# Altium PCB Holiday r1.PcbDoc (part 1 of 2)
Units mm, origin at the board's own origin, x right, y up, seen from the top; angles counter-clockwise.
Board outline 67 x 67 mm, 4 copper layers (Top Layer, Mid-Layer 1, InternalPlane1, Bottom Layer), stack 1.602 mm thick; 125 components, 139 nets, 622 pads, 401 vias.
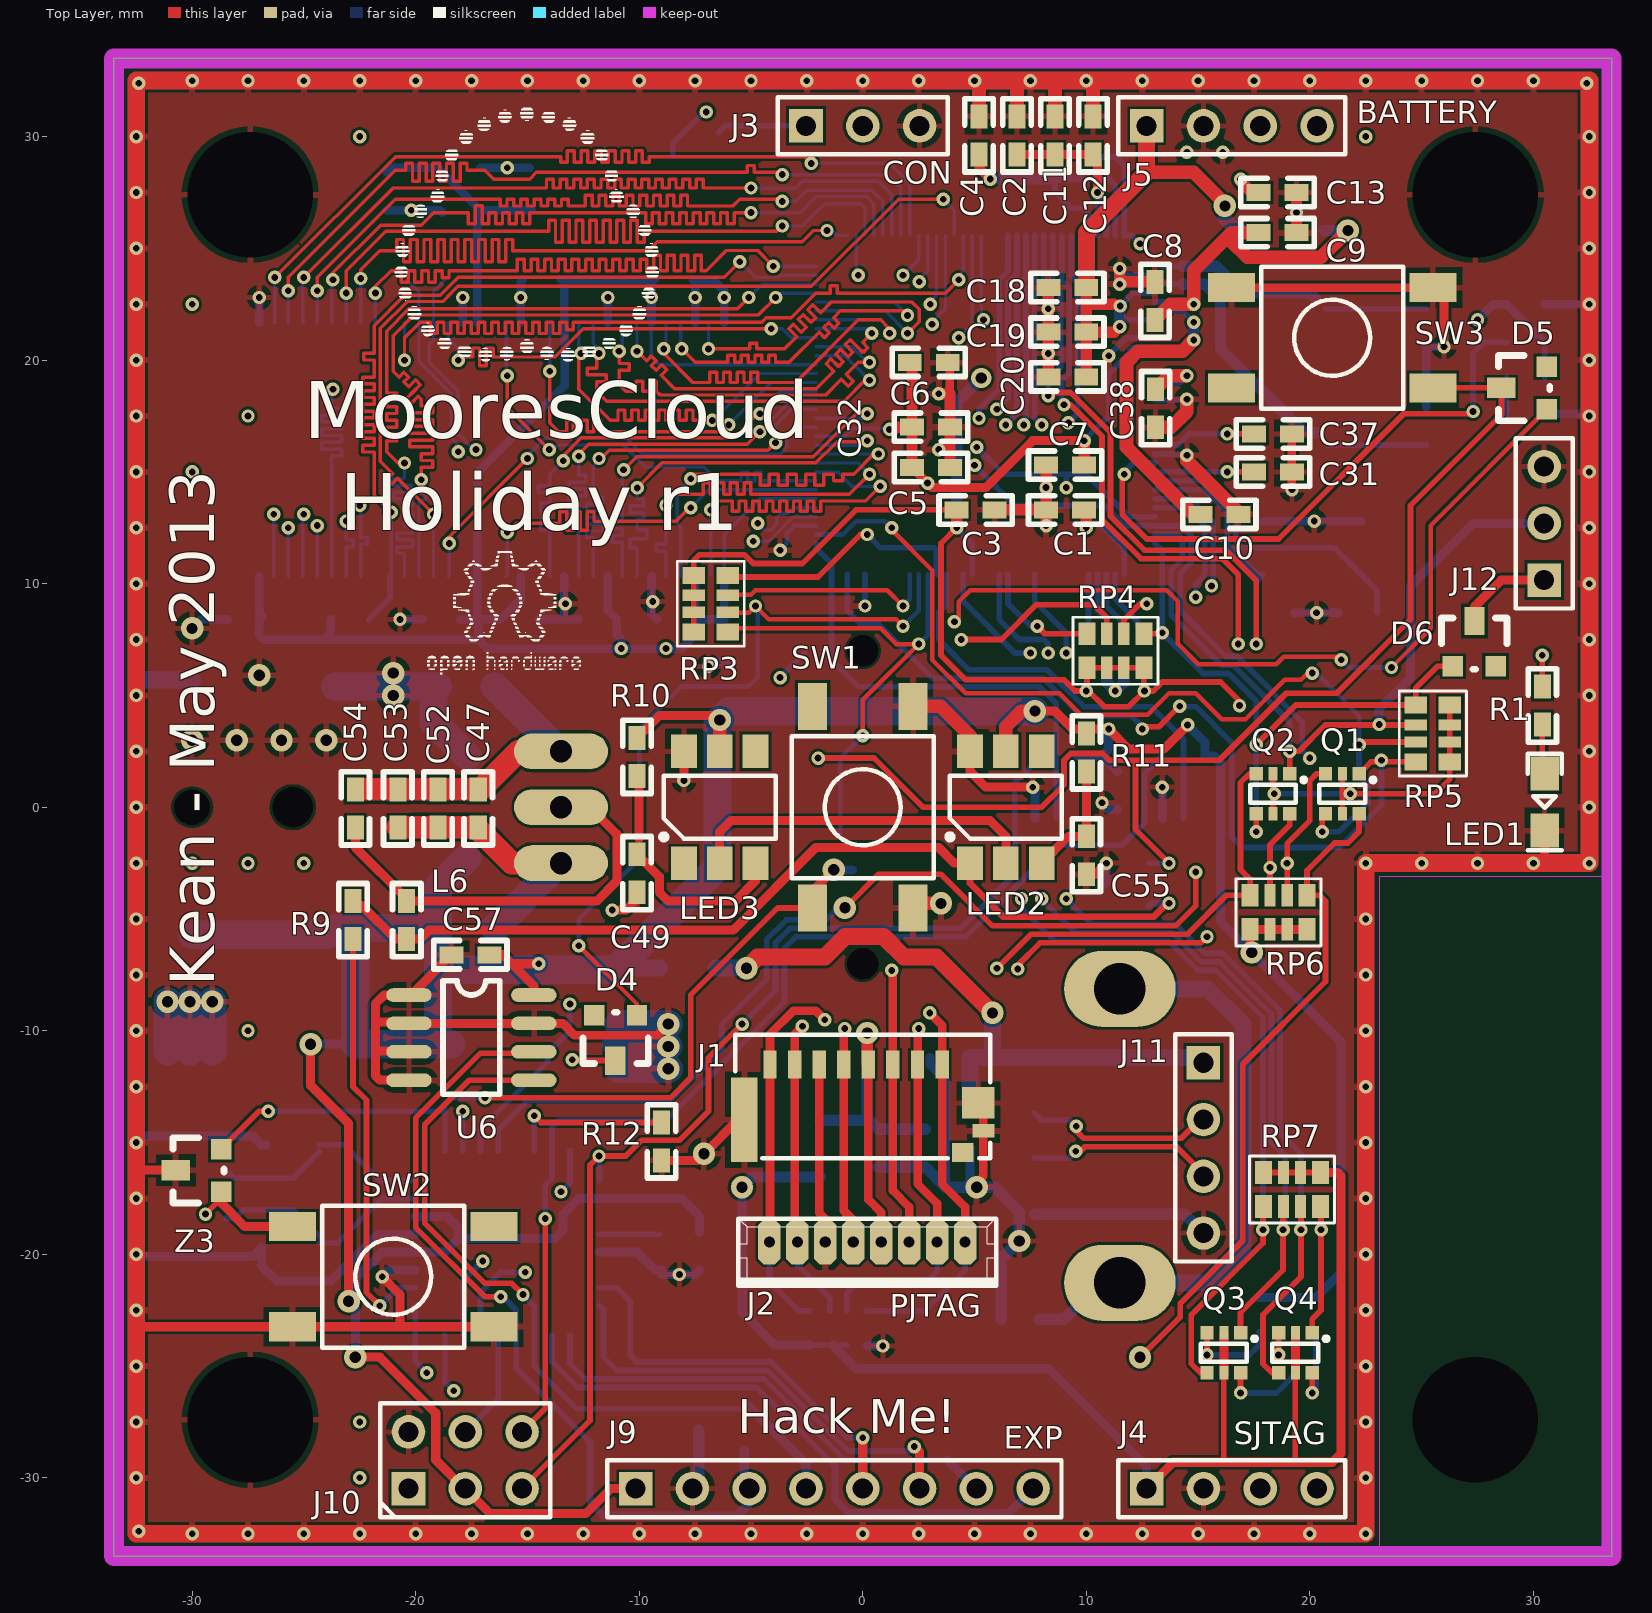
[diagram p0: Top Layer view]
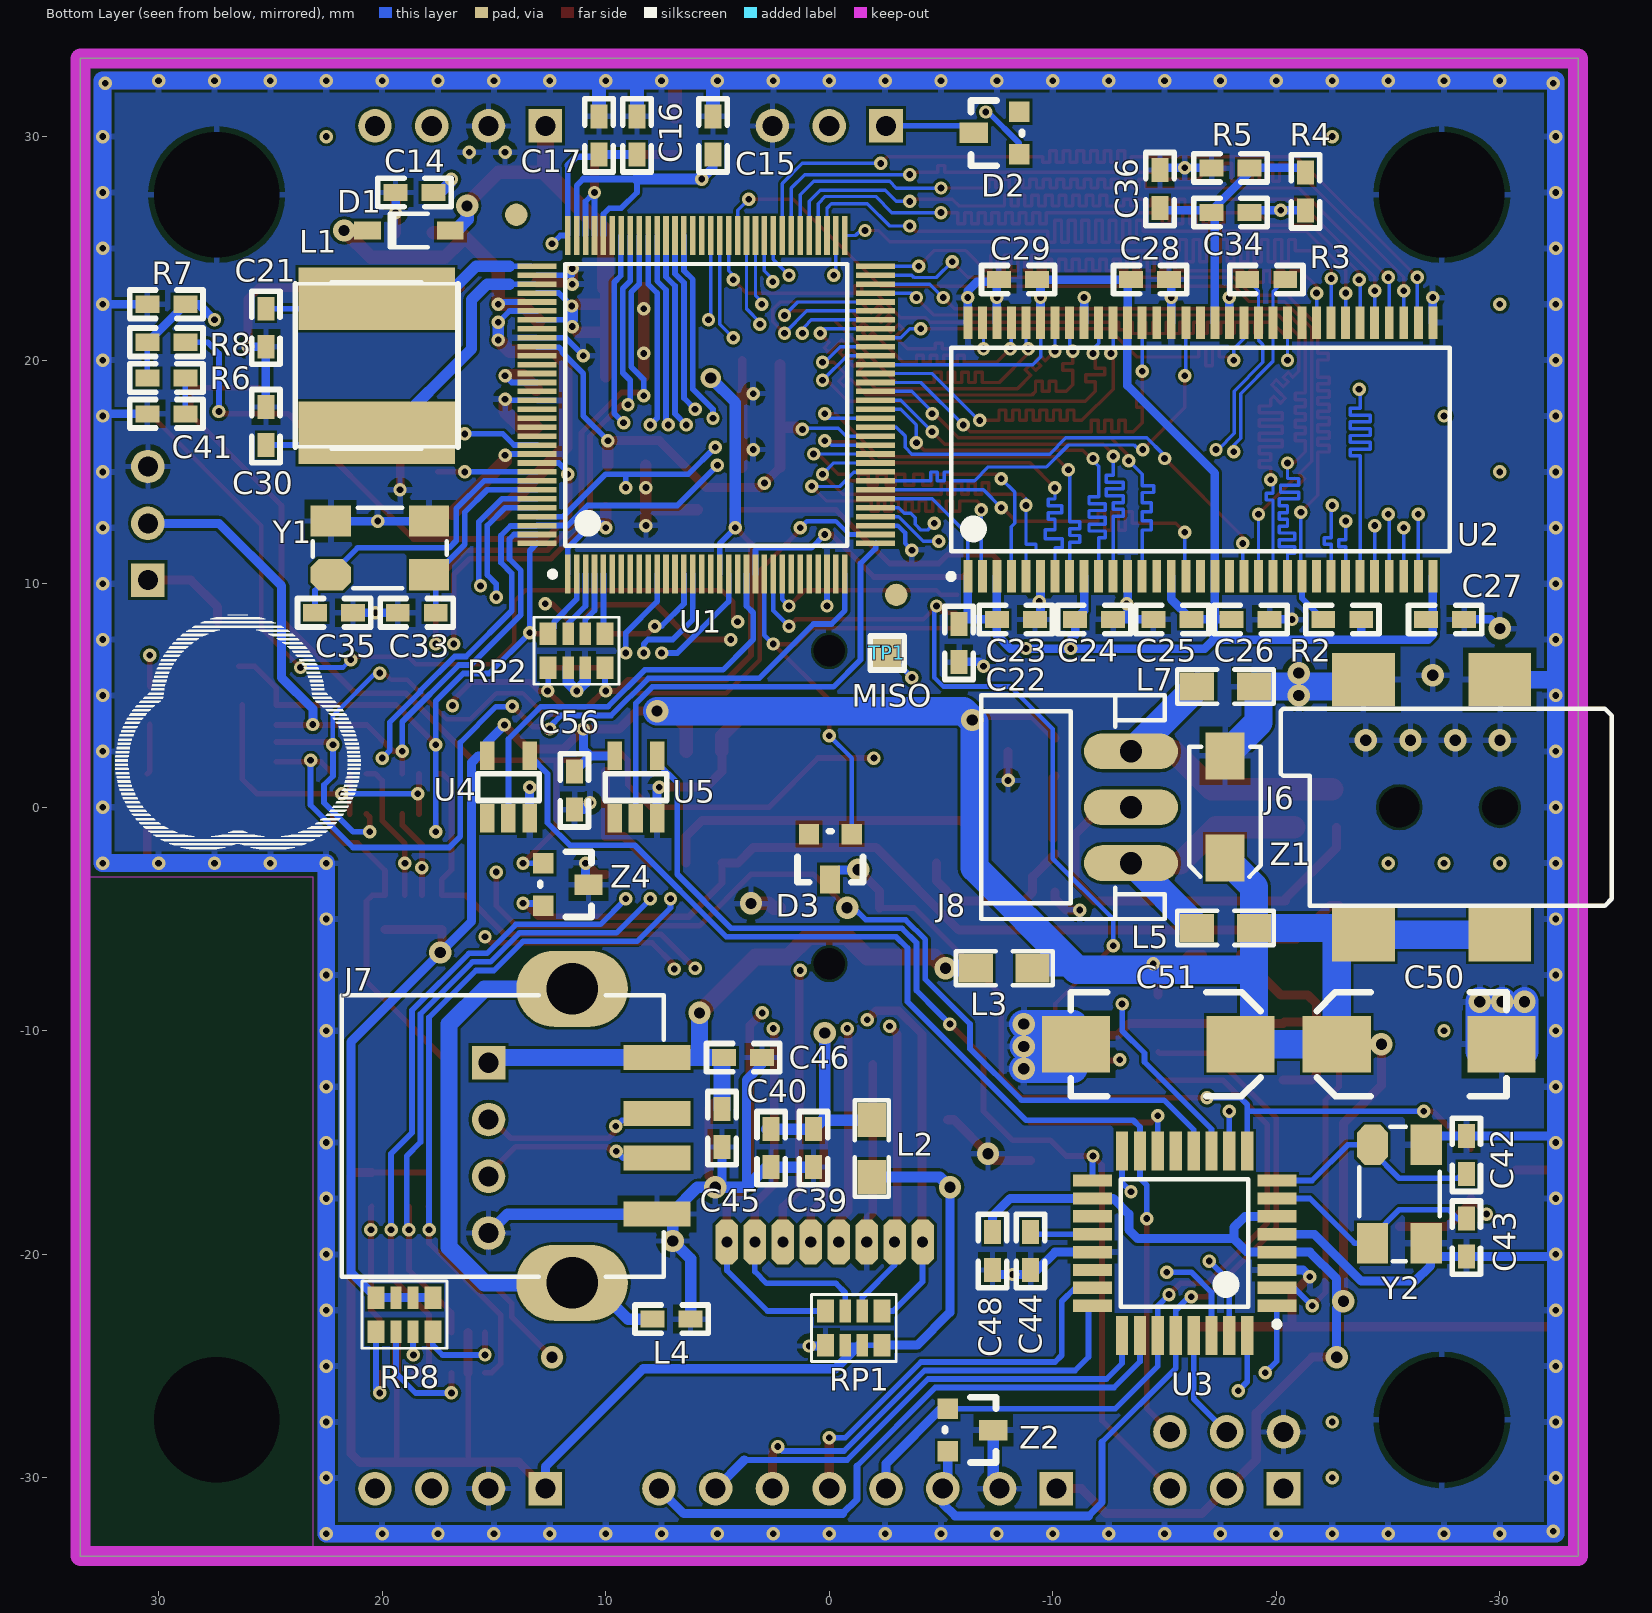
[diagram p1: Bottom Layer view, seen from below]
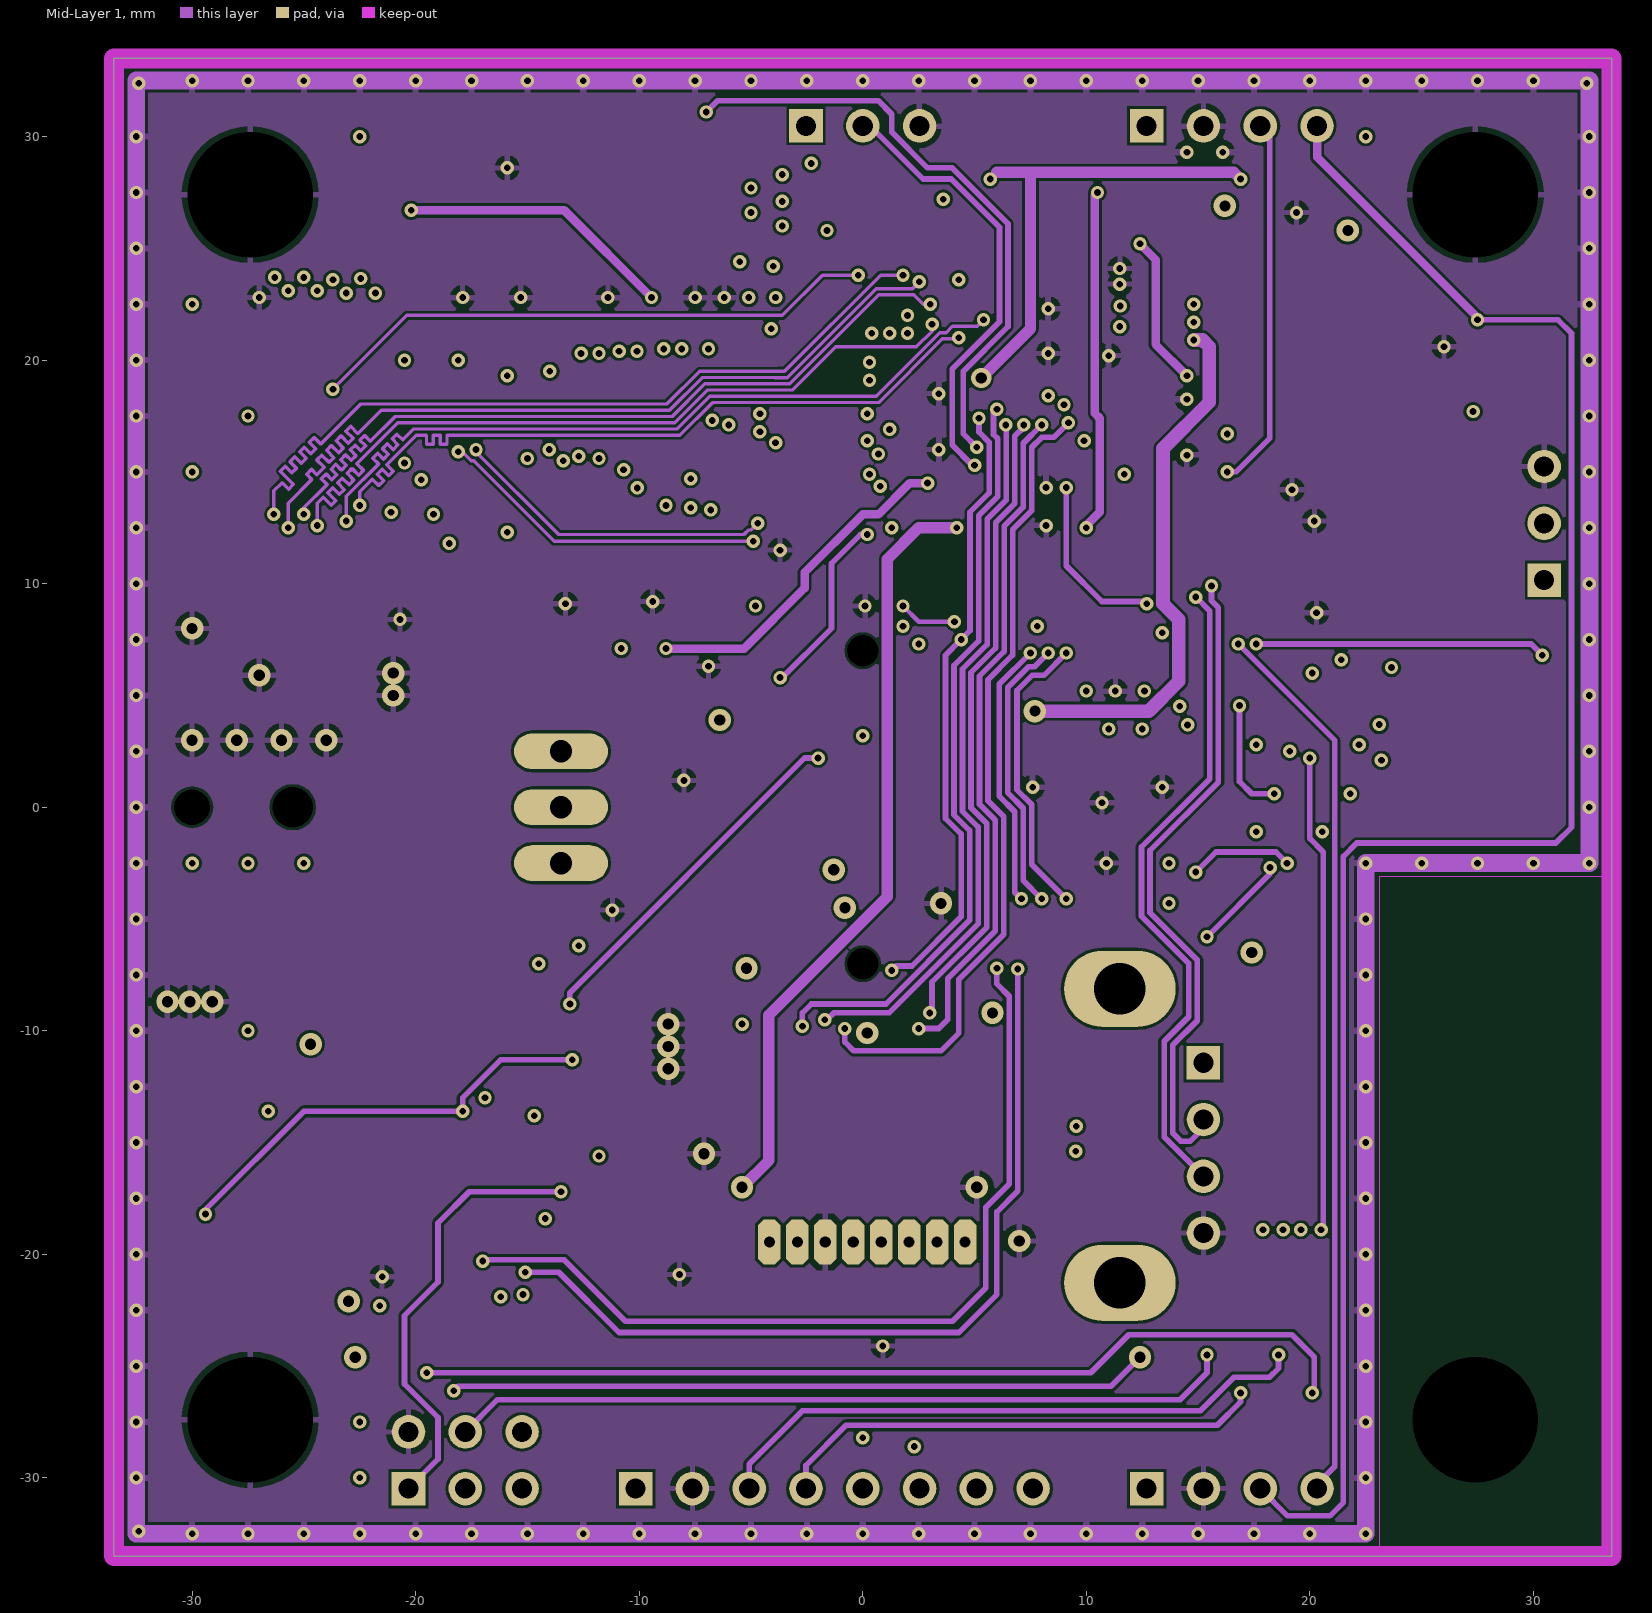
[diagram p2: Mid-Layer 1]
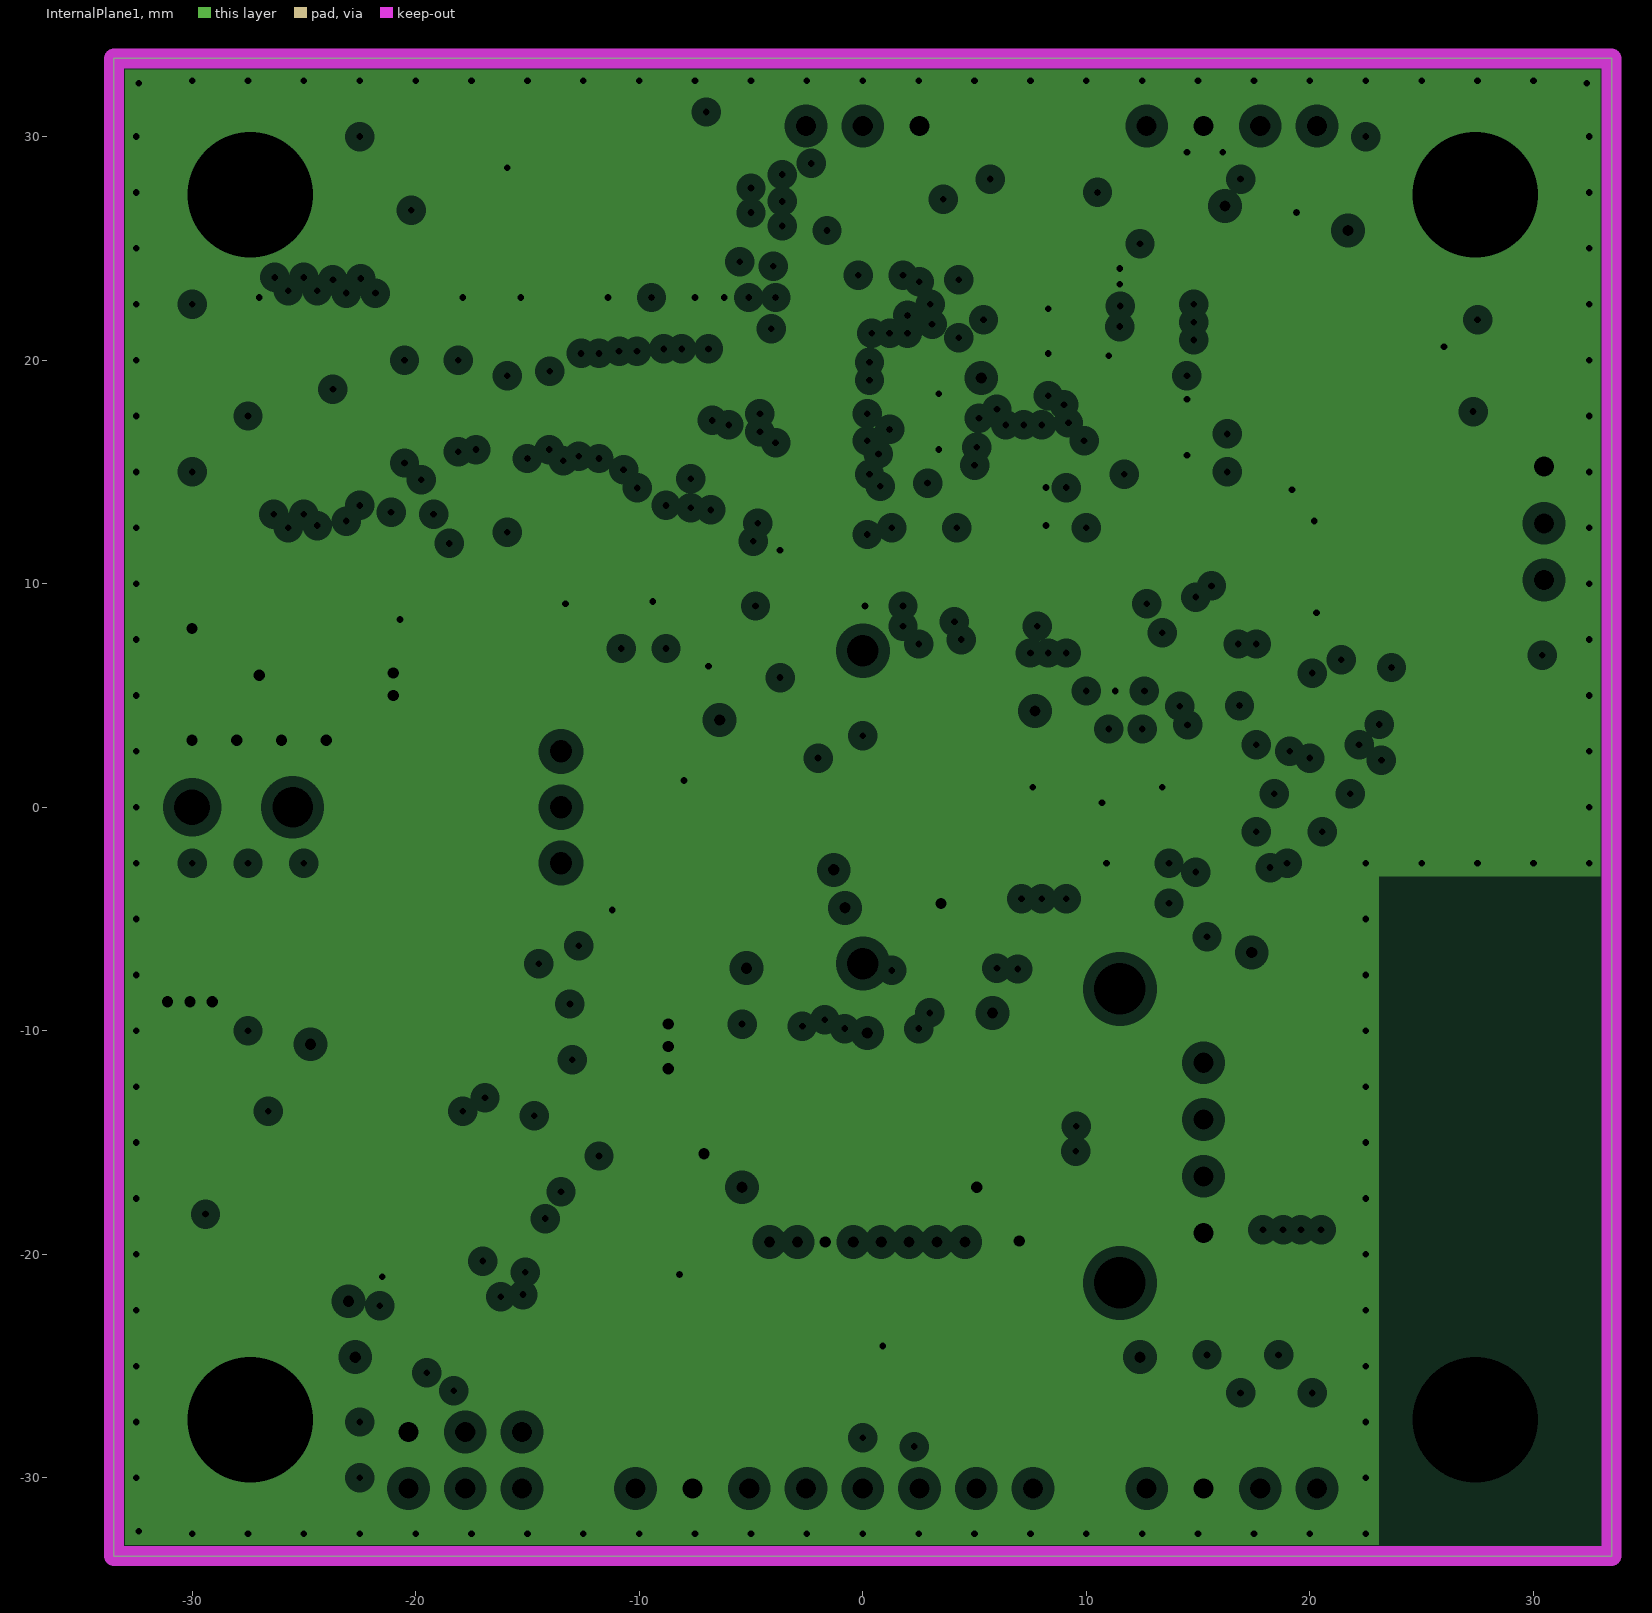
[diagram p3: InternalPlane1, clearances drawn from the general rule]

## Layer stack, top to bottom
Top Layer: signal copper 0.0356
Dielectric: prepreg 0.33, FR-4, Dk 4.8
Mid-Layer 1: signal copper 0.0356
Dielectric: prepreg 0.8, FR-4, Dk 4.8
InternalPlane1: plane copper 0.0356, net GND
Dielectric: core 0.33, FR-4, Dk 4.8
Bottom Layer: signal copper 0.0356

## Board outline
-33.5,-33.5 -33.5,33.5 33.5,33.5 33.5,-33.5

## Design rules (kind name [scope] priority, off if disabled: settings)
Clearance ClearanceUSB [(InDifferentialPairClass('USB') AND IsTrack)] p1 off: gap=0.152
Clearance [All] p2: gap=0.127
DiffPairsRouting [(InNetClass('DDR_CLK') OR InNet('USB_D_N') OR InNet('USB_D_P'))] p1: maxlimit=0.254 minlimit=0.254 mostfreqgap=0.254 maxuncoupledlength=12.7
HoleSize [All] p1: absolutevalues=TRUE maxlimit=6 minlimit=0.025 maxpercent=80.000 minpercent=20.000
MatchedLengths MatchedLengthsUSB [InNetClass('USB')] p1: tolerance=0.25 checknetsindiffpair=TRUE checkdiffpairvsdiffpair=TRUE checkothers=TRUE
MatchedLengths MatchedLengthsDDR_CLK [InNetClass('DDR_CLK')] p2: tolerance=0.1 checknetsindiffpair=TRUE checkdiffpairvsdiffpair=TRUE checkothers=TRUE
MatchedLengths MatchedLengthsDDR_CTL [(InNetClass('DDR_ADDR') OR InNetClass('DDR_CTL'))] p3: tolerance=0.5 checknetsindiffpair=TRUE checkdiffpairvsdiffpair=TRUE checkothers=TRUE
MatchedLengths MatchedLengthsDDR_DATA [InNetClass('DDR_DATA')] p4: tolerance=0.25 checknetsindiffpair=TRUE checkdiffpairvsdiffpair=TRUE checkothers=TRUE
MaxMinImpedance MaxMinImpedanceUSB [InDifferentialPairClass('USB')] p1: minimum=85.00 maximum=95.00
MinimumSolderMaskSliver [All] p1: minsoldermaskwidth=0.102
PlaneClearance [All] p1: clearance=0.508
PlaneConnect [All] p1: planeconnectstyle=Direct reliefexpansion=0.508 reliefentries=4 reliefconductorwidth=0.305 reliefairgap=0.254
PolygonConnect [All] p1: connectstyle=Relief reliefconductorwidth=0.254 reliefentries=4 polygonreliefangle="90 Angle" airgapwidth=0.254
RoutingVias [All] p1: holewidth=0.3 width=0.6 viastyle="Through Hole" minholewidth=0.3 minwidth=0.6 maxholewidth=1 maxwidth=1.27
SilkToSilkClearance [All] p1: silktosilkclearance=0
SilkToSolderMaskClearance [IsPad] p1: minsilkscreentomaskgap=0.02 clearancetoexposedcopper=TRUE
SolderMaskExpansion [All] p1: expansion=0.102
Width [All] p1: maxlimit=1.27 minlimit=0.152 preferedwidth=0.254
21 further rules are at their usual default settings.

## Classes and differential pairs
net class DDR_CTL: BA0 BA1 CAS_N CKE CS_N RAS_N WE_N
net class DDR_CLK: CLK_N CLK_P
differential pair class USB: USB_D
differential pair class DDR_CLK: CLK
net class DDR_ADDR: A0 A1 A2 A3 A4 A5 A6 A7 A8 A9 A10 A11 A12
net class DDR_DATA: D0 D1 D2 D3 D4 D5 D6 D7 D8 D9 D10 D11 D12 D13 D14 D15 DQM0 DQM1 DQS0 DQS1
component class "Holiday Aux r1": C42 C43 C44 C45 C46 C47 C48 C49 C50 C51 C52 C53 C54 C55 C57 D3 D4 D5 J6 J7 J8 J9 J10 J11 L3 L4 L5 L6 L7 LED2 LED3 R9 R10 R11 R12 RP3 SW1 SW2 SW3 U3 U6 Y2 Z1 Z2 Z3 Z4
net class A[0..12]: A0 A1 A2 A3 A4 A5 A6 A7 A8 A9 A10 A11 A12
net class D[0..15]: D0 D1 D2 D3 D4 D5 D6 D7 D8 D9 D10 D11 D12 D13 D14 D15
differential pair USB_D: +USB_D_P -USB_D_N
differential pair CLK: +CLK_P -CLK_N

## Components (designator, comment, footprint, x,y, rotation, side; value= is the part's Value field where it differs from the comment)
C1 "22u" ARA_0603 9.9,13.3 r180 top
C2 "22u" ARA_0603 6.9,29.2 r90 top
C3 "22u" ARA_0603 4.2,13.3 r0 top
C4 "22u" ARA_0603 5.2,29.2 r90 top
C5 "22u" ARA_0603 2.2,15.2 r0 top
C6 "22u" ARA_0603 2.1,19.9 r0 top
C7 "100n" ARA_0603 9.9,15.3 r180 top
C8 "22u" ARA_0603 13.075,21.8 r90 top
C9 "22u" ARA_0603 17.7,25.7 r0 top
C10 "22u" ARA_0603 15.1,13.1 r0 top
C11 "22u" ARA_0603 8.6,29.2 r90 top
C12 "100n" ARA_0603 10.3,29.2 r90 top
C13 "22u" ARA_0603 17.7,27.5 r0 top
C14 "22u" ARA_0603 17.7,27.5 r0 bottom
C15 "100n" ARA_0603 5.2,29.2 r90 bottom
C16 "22u" ARA_0603 8.6,29.2 r90 bottom
C17 "100n" ARA_0603 10.3,29.2 r90 bottom
C18 "22u" ARA_0603 10,23.25 r180 top
C19 "22u" ARA_0603 10,21.25 r180 top
C20 "22u" ARA_0603 10,19.25 r180 top
C21 "10p (DNP)" ARA_0603 25.2,22.3 r270 bottom
C22 "100n" ARA_0603 -5.8,8.2 r270 bottom
C23 "100n" ARA_0603 -7.5,8.4 r180 bottom
C24 "100n" ARA_0603 -11,8.4 r180 bottom
C25 "100n" ARA_0603 -16.2,8.4 r0 bottom
C26 "100n" ARA_0603 -18,8.4 r180 bottom
C27 "100n" ARA_0603 -26.7,8.4 r180 bottom
C28 "100n" ARA_0603 -13.5,23.6 r180 bottom
C29 "100n" ARA_0603 -9.3,23.6 r0 bottom
C30 "10p" ARA_0603 25.2,16.2 r90 bottom
C31 "100n" ARA_0603 17.5,15 r0 top
C32 "100n" ARA_0603 2.2,17 r0 top
C33 "18p" ARA_0603 17.6,8.7 r0 bottom
C34 "100n" ARA_0603 -18.8,26.6 r0 bottom
C35 "18p" ARA_0603 23,8.7 r180 bottom
C36 "100n" ARA_0603 -14.8,26.8 r90 bottom
C37 "1u" ARA_0603 17.5,16.7 r0 top
C38 "100n" ARA_0603 13.1,18.7 r270 top
C39 "22u" ARA_0603 0.7,-14.4 r270 bottom
C40 "22u" ARA_0603 2.6,-14.4 r270 bottom
C41 "100n" ARA_0603 28.8,17.6 r0 bottom
C42 "18p" ARA_0603 -28.5,-16.4 r90 bottom
C43 "18p" ARA_0603 -28.5,-18.4 r270 bottom
C44 "100n" ARA_0603 -9,-19 r270 bottom
C45 "22u" ARA_0603 4.8,-13.5 r270 bottom
C46 "100n" ARA_0603 4.7,-11.2 r180 bottom
C47 "100n" ARA_0603 -17.2,0.8 r270 top
C48 "100n" ARA_0603 -7.3,-19 r270 bottom
C49 "100n (DNP)" ARA_0603 -10.1,-3.8 r90 top
C50 "100uF, 10V, Tant" ARA_TAJD -22.7,-10.6 r180 bottom
C51 "100uF, 10V, Tant" ARA_TAJD -18.4,-10.6 r0 bottom
C52 "22u" ARA_0603 -19,-0.9 r90 top
C53 "22u" ARA_0603 -20.8,-0.9 r90 top
C54 "10p (DNP)" ARA_0603 -22.7,0.8 r270 top
C55 "100n (DNP)" ARA_0603 10,-3 r90 top
C56 "100n" ARA_0603 11.4,-0.1 r90 bottom
C57 "100n" ARA_0603 -16.7,-6.6 r180 top
D1 "1N5819 (DNP)" SOD-123 18.8,25.8 r0 bottom
D2 "BAT54" ARA_SOT-23 -8.5,29.2 r90 bottom
D3 "BAT54" ARA_SOT-23 -1,-1.2 r0 bottom
D4 "BAT54" ARA_SOT-23 -10.1,-9.3 r180 top
D5 "BAT54" ARA_SOT-23 30.6,17.8 r90 top
D6 "BAT54" ARA_SOT-23 26.4,6.3 r0 top
J1 "microSD" "MICROSD-47309-3751 WITH CARD" -0.3,-11.5 r0 top locked
J2 "PJTAG" 53047-08 0.2,-19.9 r0 top locked
J3 "CON" HDR1X3 -2.54,30.48 r180 top locked
J4 "SJTAG" HDR1X4 12.7,-30.48 r180 top locked
J5 "BATTERY" HDR1X4 12.7,30.48 r180 top locked
J6 "DC JACK" PJ-002AH-SMT -25.5,0 r0 bottom locked
J7 "USB A Female" "USB-A-FEMALE-SMT NANO WIFI" 11.5,-14.7 r270 bottom locked
J8 "JST S3B-EH" "JST-EH-S3B WITH PLUG" -13.5,0 r90 bottom locked
J9 "EXP" HDR1X8 -10.16,-30.48 r180 top locked
J10 "ISP" hdr2x3 -20.32,-30.48 r180 top locked
J11 "USBTST" HDR1X4 15.24,-11.43 r90 top locked
J12 "ACOM" HDR1X3 30.48,10.16 r270 top
L1 "22uH 1.5A" RCL_L7078 20.25,19.75 r90 bottom
L2 "470nH" ARA_0805 -1.9,-14 r270 bottom
L3 "600R 1.5A" ARA_0805 -9.1,-7.2 r0 bottom
L4 "750R 200mA" ARA_0603 6.2,-22.9 r0 bottom
L5 "120R 3.5A" ARA_0805 -19,-5.4 r0 bottom
L6 "750R 200mA" ARA_0603 -20.4,-5.9 r90 top
L7 "120R 3.5A" ARA_0805 -19,5.4 r0 bottom
LED1 "Green (DNP)" LED_0805 30.5,1.5 r270 top locked
LED2 "WS2812 (DNP)" PLCC6-IPC 6.4,0 r90 top locked
LED3 "WS2812 (DNP)" PLCC6-IPC -6.4,0 r90 top locked
Q1 "BSS138PS" ARA_SOT-363 22.2,1.5 r180 top
Q2 "BSS138PS" ARA_SOT-363 19.1,1.5 r180 top
Q3 "BSS138PS" ARA_SOT-363 16.9,-23.5 r180 top
Q4 "BSS138PS" ARA_SOT-363 20.1,-23.5 r180 top
R1 "1k (DNP)" ARA_0603 30.4,3.7 r90 top
R2 "10k" ARA_0603 -22.1,8.4 r180 bottom
R3 "120R (DNP)" ARA_0603 -18.7,23.6 r180 bottom
R4 "1k" ARA_0603 -21.3,28.4 r270 bottom
R5 "1k" ARA_0603 -18.8,28.6 r0 bottom
R6 "1k" ARA_0603 28.8,19.2 r0 bottom
R7 "100k" ARA_0603 30.5,22.5 r180 bottom
R8 "1k" ARA_0603 28.8,20.8 r0 bottom
R9 "0R" ARA_0603 -22.8,-4.2 r270 top
R10 "100R (DNP)" ARA_0603 -10.1,1.4 r90 top
R11 "100R (DNP)" ARA_0603 10,1.6 r90 top
R12 "10k" ARA_0603 -9,-15.8 r90 top
RP1 "100k" RESPACK_0603x4 -1.1,-23.3 r270 bottom
RP2 "10k" RESPACK_0603x4 11.3,7 r270 bottom
RP3 "10k" RESPACK_0603x4 -6.8,9.1 r180 top
RP4 "10k" RESPACK_0603x4 11.3,7 r270 top
RP5 "10k" RESPACK_0603x4 25.5,3.3 r0 top
RP6 "10k" RESPACK_0603x4 18.6,-4.7 r270 top
RP7 "10k" RESPACK_0603x4 19.2,-17.1 r90 top
RP8 "10k" RESPACK_0603x4 19,-22.7 r90 bottom
SW1 "TACTILE_SWITCH" TACTILE_SWITCH_SMD 0,0 r90 top locked
SW2 "TACTILE_SWITCH" TACTILE_SWITCH_SMD -21,-21 r0 top locked
SW3 "TACTILE_SWITCH" TACTILE_SWITCH_SMD 21,21 r180 top locked
TP1 "MISO" SMD_TESTTERMINAL -2.6,6.9 r180 bottom
U1 "MCIMX233DAG4B" LQFP128 5.5,18 r90 bottom locked
U2 "H5DU5162ETR-E3C" TSOP-II-66 -16.6,16 r90 bottom locked
U3 "ATMEGA328" TQFP32 -15.9,-19.5 r0 bottom locked
U4 "MC74VHC1GT50" ARA_SOT-23-5L 15.3,-0.5 r180 bottom
U5 "MC74VHC1GT50" ARA_SOT-23-5L 9.6,-0.5 r180 bottom
U6 "8kB EEPROM" SO-8 -20.3,-8.4 r180 top
Y1 "24Mhz" CRYSTAL_ABMM2 20.1,11.6 r180 bottom
Y2 "16MHz" CRYSTAL_ABMM2 -25.5,-17.3 r270 bottom
Z1 "SMBJ TVS" ARA_DO-214AC -17.7,2.3 r270 bottom
Z2 "GSOT05C" ARA_SOT-23 -5.3,-26.9 r270 bottom
Z3 "GSOT05C" ARA_SOT-23 -28.7,-17.2 r90 top
Z4 "GSOT05C" ARA_SOT-23 12.8,-2.5 r270 bottom

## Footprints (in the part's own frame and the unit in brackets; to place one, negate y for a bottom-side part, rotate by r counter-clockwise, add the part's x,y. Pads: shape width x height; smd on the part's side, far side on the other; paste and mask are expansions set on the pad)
53047-08 [mm]
  oct 1.008x2.016 hole 0.5: 1(4.375,0.45) 2(3.125,0.45) 3(1.875,0.45) 4(0.625,0.45) 5(-0.625,0.45) 6(-1.875,0.45) 7(-3.125,0.45) 8(-4.375,0.45)
  silkscreen extent -5.77,-1.5 5.78,1.5
ARA_0603 [mil]
  rect 42x30 smd: 1(0,0) 2(66.91,0)
  silkscreen extent -31,-25 98,25, body extent 0,-16 67,16, height 20
ARA_0805 [mil]
  rect 60x50 smd: 1(0,0) 2(100,0)
  silkscreen extent -35,-30 135,30, body extent 0,-24 102,24, height 24
ARA_DO-214AC [mm]
  rect 2.1x1.75 smd: 1(0,0) 2(4.572,0)
  silkscreen extent -0.4,-1.6 5.4,1.6, body extent -0.4,-1.6 4.9,1.6, height 2.3
ARA_SOT-23 [mil]
  rect 36x36 smd: 1(0,0) 2(75,0)
  rect 36x50 smd: 3(38,80)
  silkscreen extent -20,-5 95,85, body extent -26,8 101,71, height 39
ARA_SOT-23-5L [mm]
  rect 0.65x1.27 smd: 1(0,0) 2(0.95,0) 3(1.9,0) 4(1.9,2.8) 5(0,2.8)
  silkscreen extent -0.43,0.8 2.32,2, body extent -0.42,0.8 2.32,2, height 1.45
ARA_SOT-363 [mm] "SOT-363/SC-88"
  rect 0.6x0.6 smd paste-0.05 mask+0.05: 1(0,0) 3(1.5,0) 4(1.5,1.8) 6(0,1.8)
  rect 0.4x0.6 smd paste-0.05 mask+0.05: 2(0.75,0) 5(0.75,1.8)
  silkscreen extent -0.72,0.18 1.78,1.3, body extent -0.25,0.25 1.75,1.55, height 0.95
ARA_TAJD [mil]
  rect 120x100 smd: 1(0,0) 2(290,0)
  silkscreen extent -35,-92 299,92, body extent 0,-85 287,85, height 115
CRYSTAL_ABMM2 [mm] "Abracon ABMM2 Low Profile Quartz Crystal"
  oct 1.8x1.4 smd: 1(-2.2,-1.2)
  rect 1.8x1.4 smd: 2(2.2,-1.2) 3(2.2,1.2) 4(-2.2,1.2)
  silkscreen extent -3,-1.8 3,1.8, body extent -3,-1.8 3,1.8, height 1.2
HDR1X3 [mm] "Connector; Header; 3 Position"
  rect 1.5x1.5 hole 0.9: 1(0,0)
  round 1.5 hole 0.9: 2(-2.54,0) 3(-5.08,0)
  silkscreen extent -6.35,-1.27 1.27,1.27
HDR1X4 [mm] "Connector; Header; 4 Position"
  rect 1.5x1.5 hole 0.9: 1(0,0)
  round 1.5 hole 0.9: 2(-2.54,0) 3(-5.08,0) 4(-7.62,0)
  silkscreen extent -8.89,-1.27 1.27,1.27
HDR1X8 [mm] "Connector; Header; 8 Position"
  rect 1.5x1.5 hole 0.9: 1(0,0)
  round 1.5 hole 0.9: 2(-2.54,0) 3(-5.08,0) 4(-7.62,0) 5(-10.16,0) 6(-12.7,0) 7(-15.24,0) 8(-17.78,0)
  silkscreen extent -19.05,-1.27 1.27,1.27
hdr2x3 [mm] "Connector; Header; 6 Position; Dual Row"
  rect 1.5x1.5 hole 0.9: 1(0,0)
  round 1.5 hole 0.9: 2(-2.54,0) 3(-5.08,0) 4(-5.08,-2.54) 5(-2.54,-2.54) 6(0,-2.54)
  silkscreen extent -6.35,-3.81 1.27,1.27
"JST-EH-S3B WITH PLUG" [mm] "JST EH Side Entry 3 way - with plug"
  oval 1.6x4.2 hole 1: 1(-2.5,0) 2(0,0) 3(2.5,0)
  silkscreen extent -5,-1.5 5,6.7, body extent -5,-1.5 5,8.85, height 4.35
LED_0805 [mil]
  rect 60x50 smd: A(0,0) K(100,0)
  silkscreen extent -35,-30 135,30, body extent 0,-24 102,24, height 24
LQFP128 [mm] "LQFP, 128-Leads, Body 14.00x14.00mm, Pitch 0.40mm, IPC Medium Density"
  rect 1.75x0.25 smd: 1(-7.575,6.2) 2(-7.575,5.8) 3(-7.575,5.4) 4(-7.575,5) 5(-7.575,4.6) 6(-7.575,4.2) 7(-7.575,3.8) 8(-7.575,3.4) 9(-7.575,3) 10(-7.575,2.6) 11(-7.575,2.2) 12(-7.575,1.8) 13(-7.575,1.4) 14(-7.575,1) 15(-7.575,0.6) 16(-7.575,0.2) 17(-7.575,-0.2) 18(-7.575,-0.6) 19(-7.575,-1) 20(-7.575,-1.4) 21(-7.575,-1.8) 22(-7.575,-2.2) 23(-7.575,-2.6) 24(-7.575,-3) 25(-7.575,-3.4) 26(-7.575,-3.8) 27(-7.575,-4.2) 28(-7.575,-4.6) 29(-7.575,-5) 30(-7.575,-5.4) 31(-7.575,-5.8) 32(-7.575,-6.2) 65(7.575,-6.2) 66(7.575,-5.8) 67(7.575,-5.4) 68(7.575,-5) 69(7.575,-4.6) 70(7.575,-4.2) 71(7.575,-3.8) 72(7.575,-3.4) 73(7.575,-3) 74(7.575,-2.6) 75(7.575,-2.2) 76(7.575,-1.8) 77(7.575,-1.4) 78(7.575,-1) 79(7.575,-0.6) 80(7.575,-0.2) 81(7.575,0.2) 82(7.575,0.6) 83(7.575,1) 84(7.575,1.4) 85(7.575,1.8) 86(7.575,2.2) 87(7.575,2.6) 88(7.575,3) 89(7.575,3.4) 90(7.575,3.8) 91(7.575,4.2) 92(7.575,4.6) 93(7.575,5) 94(7.575,5.4) 95(7.575,5.8) 96(7.575,6.2)
  rect 0.25x1.75 smd: 33(-6.2,-7.575) 34(-5.8,-7.575) 35(-5.4,-7.575) 36(-5,-7.575) 37(-4.6,-7.575) 38(-4.2,-7.575) 39(-3.8,-7.575) 40(-3.4,-7.575) 41(-3,-7.575) 42(-2.6,-7.575) 43(-2.2,-7.575) 44(-1.8,-7.575) 45(-1.4,-7.575) 46(-1,-7.575) 47(-0.6,-7.575) 48(-0.2,-7.575) 49(0.2,-7.575) 50(0.6,-7.575) 51(1,-7.575) 52(1.4,-7.575) 53(1.8,-7.575) 54(2.2,-7.575) 55(2.6,-7.575) 56(3,-7.575) 57(3.4,-7.575) 58(3.8,-7.575) 59(4.2,-7.575) 60(4.6,-7.575) 61(5,-7.575) 62(5.4,-7.575) 63(5.8,-7.575) 64(6.2,-7.575) 97(6.2,7.575) 98(5.8,7.575) 99(5.4,7.575) 100(5,7.575) 101(4.6,7.575) 102(4.2,7.575) 103(3.8,7.575) 104(3.4,7.575) 105(3,7.575) 106(2.6,7.575) 107(2.2,7.575) 108(1.8,7.575) 109(1.4,7.575) 110(1,7.575) 111(0.6,7.575) 112(0.2,7.575) 113(-0.2,7.575) 114(-0.6,7.575) 115(-1,7.575) 116(-1.4,7.575) 117(-1.8,7.575) 118(-2.2,7.575) 119(-2.6,7.575) 120(-3,7.575) 121(-3.4,7.575) 122(-3.8,7.575) 123(-4.2,7.575) 124(-4.6,7.575) 125(-5,7.575) 126(-5.4,7.575) 127(-5.8,7.575) 128(-6.2,7.575)
  silkscreen extent -7.7,-6.3 6.3,7, body extent -7,-7 7,7, height 1.6
"MICROSD-47309-3751 WITH CARD" [mm] "Molex MicroSD Connector - Push/Pull - 3.75mm with Card"
  rect 0.6x1.25 smd: 1(3.85,0) 2(2.75,0) 3(1.65,0) 4(0.55,0) 5(-0.55,0) 6(-1.65,0) 7(-2.75,0) 8(-3.85,0)
  rect 1.2x3.79 smd: G1(-5,-2.48)
  rect 1.45x1.4 smd: G2(5.475,-1.725)
  rect 1x0.6 smd: G3(5.7,-2.975)
  rect 0.95x0.85 smd: G4(4.775,-3.95)
  silkscreen extent -5.4,-4.2 6,1.32, body extent -5.4,-14 6.1,1.4, height 3.75
PJ-002AH-SMT [mm] "CUI High Current SMT DC Jack"
  round 0 hole 1.6 unplated: 0(-4.5,0)
  round 0 hole 1.8 unplated: 0(0,0)
  rect 2.8x2.4 smd: 1(-4.5,5.7) 1(1.6,5.7) 2(-4.5,-5.7) 3(1.6,-5.7)
  silkscreen extent -9.5,-4.4 5.3,4.4, body extent -9.5,-6.3 5.3,6.3, height 11.2
PLCC6-IPC [mm] "Leaded Chip Carrier, 12-Leads, Body 9.90x5.40mm, Pitch 1.600mm, IPC Medium Density"
  rect 1.5x1.15 smd: 1(-2.5,1.6) 2(-2.5,0) 3(-2.5,-1.6) 4(2.5,-1.6) 5(2.5,0) 6(2.5,1.6)
  silkscreen extent -1.45,-2.5 1.4,2.62, body extent -2.5,-2.5 2.5,2.5, height 1.61
RCL_L7078 [mm] "7x7.8mm Inductor"
  rect 2.8x7 smd: 1(3,0) 2(-3,0)
  silkscreen extent -3.73,-3.64 3.76,3.64, body extent -3.8,-3.6 3.8,3.6, height 4.5
RESPACK_0603x4 [mil] "Resistor Pack 0603 x 4 (1206)"
  rect 40x30 smd: 1.1(-30,50) 1.2(30,50) 4.1(-30,-50) 4.2(30,-50)
  rect 40x20 smd: 2.1(-30,15) 2.2(30,15) 3.1(-30,-15) 3.2(30,-15)
  silkscreen extent -59,-75 59,75, body extent -40,-66 43,67, height 26
SMD_TESTTERMINAL [mm]
  rect 1.27x1.27 smd paste-2: 1(0,0)
  silkscreen extent -0.76,-0.76 0.76,0.76
SO-8 [mil]
  oval 80x24 smd: 1(0,0) 2(0,50) 3(0,100) 4(0,150) 5(-220,150) 6(-220,100) 7(-220,50) 8(-220,0)
  silkscreen extent -160,-25 -60,175
SOD-123 [mm] "SOD-123; 2 Leads; Body 2.7 x 1.6 mm, (LxW)"
  rect 1.2x0.8 smd: 1(-1.85,0) 2(1.85,0)
  silkscreen extent -0.85,-0.75 0.85,0.75
TACTILE_SWITCH_SMD [mm]
  rect 2.1x1.3 smd: 1(-4.51,2.24) 2(4.51,2.24) 3(-4.51,-2.24) 4(4.51,-2.24)
  silkscreen extent -3.17,-3.18 3.18,3.17, body extent -5,-3 5,3, height 5.1
TQFP32 [mm] "TQFP, 32-Leads, Body 7.00x7.00mm, Pitch 0.80mm, IPC Medium Density"
  rect 1.75x0.55 smd: 1(-4.125,2.8) 2(-4.125,2) 3(-4.125,1.2) 4(-4.125,0.4) 5(-4.125,-0.4) 6(-4.125,-1.2) 7(-4.125,-2) 8(-4.125,-2.8) 17(4.125,-2.8) 18(4.125,-2) 19(4.125,-1.2) 20(4.125,-0.4) 21(4.125,0.4) 22(4.125,1.2) 23(4.125,2) 24(4.125,2.8)
  rect 0.55x1.75 smd: 9(-2.8,-4.125) 10(-2,-4.125) 11(-1.2,-4.125) 12(-0.4,-4.125) 13(0.4,-4.125) 14(1.2,-4.125) 15(2,-4.125) 16(2.8,-4.125) 25(2.8,4.125) 26(2,4.125) 27(1.2,4.125) 28(0.4,4.125) 29(-0.4,4.125) 30(-1.2,4.125) 31(-2,4.125) 32(-2.8,4.125)
  silkscreen extent -4.25,-2.85 2.85,3.75, body extent -3.5,-3.5 3.5,3.5, height 1.2
TSOP-II-66 [mm] "TSOP, 66-Leads, Body 22.22x10.16mm, Pitch 0.65mm, IPC Medium Density"
  rect 1.45x0.4 smd: 1(-5.675,10.4) 2(-5.675,9.75) 3(-5.675,9.1) 4(-5.675,8.45) 5(-5.675,7.8) 6(-5.675,7.15) 7(-5.675,6.5) 8(-5.675,5.85) 9(-5.675,5.2) 10(-5.675,4.55) 11(-5.675,3.9) 12(-5.675,3.25) 13(-5.675,2.6) 14(-5.675,1.95) 15(-5.675,1.3) 16(-5.675,0.65) 17(-5.675,0) 18(-5.675,-0.65) 19(-5.675,-1.3) 20(-5.675,-1.95) 21(-5.675,-2.6) 22(-5.675,-3.25) 23(-5.675,-3.9) 24(-5.675,-4.55) 25(-5.675,-5.2) 26(-5.675,-5.85) 27(-5.675,-6.5) 28(-5.675,-7.15) 29(-5.675,-7.8) 30(-5.675,-8.45) 31(-5.675,-9.1) 32(-5.675,-9.75) 33(-5.675,-10.4) 34(5.675,-10.4) 35(5.675,-9.75) 36(5.675,-9.1) 37(5.675,-8.45) 38(5.675,-7.8) 39(5.675,-7.15) 40(5.675,-6.5) 41(5.675,-5.85) 42(5.675,-5.2) 43(5.675,-4.55) 44(5.675,-3.9) 45(5.675,-3.25) 46(5.675,-2.6) 47(5.675,-1.95) 48(5.675,-1.3) 49(5.675,-0.65) 50(5.675,0) 51(5.675,0.65) 52(5.675,1.3) 53(5.675,1.95) 54(5.675,2.6) 55(5.675,3.25) 56(5.675,3.9) 57(5.675,4.55) 58(5.675,5.2) 59(5.675,5.85) 60(5.675,6.5) 61(5.675,7.15) 62(5.675,7.8) 63(5.675,8.45) 64(5.675,9.1) 65(5.675,9.75) 66(5.675,10.4)
  silkscreen extent -5.8,-11.15 4.55,11.28, body extent -5.15,-11.15 5.15,11.15, height 1.2
"USB-A-FEMALE-SMT NANO WIFI" [mm] "USB A Socket SMT - with Nano WiFi Module"
  rect 1.12x3 smd: 1(-3.5,3.8) 2(-1,3.8) 3(1,3.8) 4(3.5,3.8)
  oval 3.4x5 hole 2.3: G1(-6.575,0) G2(6.575,0)
  silkscreen extent -6.3,-10.3 6.3,4.1, body extent -7.8,-20.4 7.8,4.96, height 7.7

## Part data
C1 C2 C3 C4 C5 C6 C7 C8 C9 C10 C11 C12 C13 C14 C15 C16 C17 C18 C19 C20 C21 C22 C23 C24 C25 C26 C27 C28 C29 C30 C31 C32 C33 C34 C35 C36 C37 C38 C39 C40 C41 C42 C43 C44 C45 C46 C47 C48 C49 C52 C53 C54 C55 C56 C57: library part CAP, "Capacitor"
C50 C51: library part "Cap Pol3", "Polarized Capacitor (Surface Mount)"
D1: library part "DIODE SCHOTTKY", "Schottky Diode 1N5819HW (DNP)"
D2 D3 D4 D5 D6: "Schottky Diode"
J1: "microSD Socket Push/Pull"
J2 J9: library part CON8, "Connector"
J3 J8 J12: library part CON3, "Connector"
J4 J5 J11: library part CON4, "Connector"
J6: library part DCJACK
J7: library part USB_A_FEMALE
J10: library part CON6, "Connector"
L1: library part Inductor, "Inductor"
L2 L3 L4 L5 L6 L7: library part Inductor, "Ferrite"
LED1: library part LED, "LED"
LED2 LED3: library part WS2812, "WorldSemi WS2812 Smart RGB LED"
Q1 Q2 Q3 Q4: "Dual N Channel MOSFET"
R1 R2 R3 R4 R5 R6 R7 R8 R9 R10 R11 R12: library part "Res Semi", "Resistor"
RP1 RP2: library part RESISTOR_PACK_4_1206, "Resistor Pack 4x0603"
RP3 RP4 RP5 RP6 RP7 RP8: library part RESISTOR_PACK_4_1206_SPLIT, "Resistor Pack 4x0603"
SW1 SW2 SW3: "Pushbutton SMT"
TP1: library part TESTTERMINAL, "Test Point"
U1: "Freescale i.MX233 128 pin LQFP package"
U2: "SDRAM DDR400 66TSOP-II"
U3: library part ATMEGA328-TQFP32, "ATMEGA328 - TQFP"
U4 U5: "CMOS Logic Level Shifter"
U6: library part "EEPROM I2C", "CAT24C64W EEPROM I2C"
Y1 Y2: library part CRYSTAL_ABMM2, "ABMM2 SMD Crystal"
Z1: library part "TVS SMBJ", "SMBJ Unidirectional TVS"
Z2 Z3 Z4: library part GSOT03C, "Two-Line ESD-Protection in SOT23"

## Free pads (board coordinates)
  round 0 hole 5.6: 0(-27.4,-27.4) 0(-27.4,27.4) 0(27.4,-27.4) 0(27.4,27.4)
  round 0 hole 1.4 unplated: 0(0,-7) 0(0,7)
  round 1 smd far side paste-1 mask+1: 1(-3,9.5) 2(14,26.5)

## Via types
v1: diameter 0.6, hole 0.3, Top Layer to Bottom Layer, tented both sides, 365 vias
v2: diameter 1, hole 0.5, Top Layer to Bottom Layer, tented both sides, 33 vias
v3: diameter 0.6, hole 0.3, Top Layer to Bottom Layer, 2 vias
v4: diameter 0.9, hole 0.5, Top Layer to Bottom Layer, tented both sides, 1 vias

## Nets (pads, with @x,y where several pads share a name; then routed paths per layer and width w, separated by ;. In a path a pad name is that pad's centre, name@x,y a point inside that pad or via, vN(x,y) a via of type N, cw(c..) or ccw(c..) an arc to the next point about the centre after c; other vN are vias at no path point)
2V5: C5.1 C6.1 C7.1 C22.1 C23.1 C24.1 C25.1 C26.1 C27.1 C28.1 C29.1 C32.1 C34.1 R2.2 R4.2 U1.38 U1.45 U1.53 U1.106 U2.1 U2.3 U2.9 U2.15 U2.18 U2.33 U2.55 U2.61 | length 133.6
  Top Layer w0.406: C5.1@2.2,15.2 v1(2.9,14.5) 3.1,14.3 5.5,14.3 7.6,16.4 v1(9.9,16.4)
  Top Layer w0.508: v1(1.2,16.9) 1.4,16.9 1.5,17 C32.1@2.2,17 ; C5.1@2.2,15.2 C32.1@2.2,17 ; C6.1@2.2,19.8 C32.1@2.2,17 ; C7.1@9.9,15.3 v1(9.9,16.4)
  Mid-Layer 1 w0.381: v1(-20.2,26.7) -13.35,26.7 v1(-9.45,22.8) ; v1(-8.8,7.1) -5.3,7.1 -2.6,9.8 -2.6,10.5 0,13.1 0.7,13.1 2.1,14.5 v1(2.9,14.5)
  Bottom Layer w0.152: U2.61@-9.45,21.675 -9.454,21.671 -9.454,20.154 -9.1,19.8 U1.53@-2.075,19.8 ; U2.1@-6.2,10.325 -6.2,12.2 -4.6,13.8 U1.38@-2.075,13.8 ; U1.45@-2.075,16.6 -0.761,16.6 -0.411,16.95 1.15,16.95 v1(1.2,16.9)
  Bottom Layer w0.254: v1(9.9,16.4) 11,17.5 11,19.4 11.946,20.346 11.946,20.43 12.095,20.579 13.054,20.579 U1.106@13.075,20.6
  Bottom Layer w0.381: C27.1@-27,8.4 -27,7.7 -26.8,7.5 -24.1,7.5 ; U2.33@-27,10.325 -27,8.7 C27.1@-26.85,8.55 ; R2.2@-23.8,8.4 -23.8,7.8 -24.1,7.5 ; R4.2@-21.3,26.7 v1(-20.2,26.7) -18.9,26.7 C34.1@-18.8,26.6 ; C26.1@-18,8.4 -17.2,8.4 ; U2.15@-15.3,10.325 -15.3,9.3 C25.1@-16.2,8.4 ; U2.55@-13.35,21.675 -13.35,23.45 C28.1@-13.5,23.6 C29.1@-9.3,23.6 ; U2.55@-13.337,21.8 -13.337,18.863 -17.25,14.95 U2.18@-17.25,10.325 -17.25,8.45 -17.2,8.4 ; U2.9@-11.4,10.325 -11.4,8.8 C24.1@-11,8.4 -11,7.7 -10.8,7.5 v1(-10.8,7.1) ; U2.61@-9.45,21.675 v1(-9.45,22.8) C29.1@-9.45,23.45 ; v1(-8.8,7.1) -8.1,7.1 ; U2.3@-7.5,10.325 C23.1@-7.5,8.4 ; U2.1@-6.2,10.325 -6.2,8.4 C23.1@-7.5,8.4 ; -24.1,7.5 -17.2,7.5 ; -17.2,7.5 -17.2,8.4 ; -17.2,7.5 -16.8,7.1 v1(-10.8,7.1) ; -17.2,8.4 C25.1@-16.2,8.4 ; -17.2,8.4 C25.1@-16.2,8.4 ; v1(-10.8,7.1) -8.1,7.1 ; -8.1,7.1 -7.5,7.7 C23.1@-7.5,8.4
3V3: C3.1 C4.1 C13.1 C14.1 C15.1 J4.1 L2.2 Q1.2 Q1.5 Q2.2 Q2.5 Q3.2 Q3.5 Q4.2 Q4.5 RP1.1.2 RP1.2.2 RP1.3.2 RP2.1.2 RP2.4.2 RP3.1.2 RP3.2.2 RP3.3.2 RP3.4.2 RP4.1.2 RP4.2.2 RP4.3.2 RP4.4.2 RP5.1.2 RP5.2.2 RP5.3.2 RP5.4.2 RP7.1.2 RP7.2.2 RP7.3.2 RP7.4.2 U1.18 U1.92 U1.95 | length 215.4
  Top Layer w0.254: RP3.1.2@-7.562,7.83 RP3.2.2@-7.562,8.719 RP3.3.2@-7.562,9.481 RP3.4.2@-7.562,10.37 -7.562,11.038 -7.3,11.3 -5.3,11.3 -4.9,10.9 -2.7,10.9 -0.3,13.3 C3.1@4.2,13.3 ; v1(4.2,12.5) 3.5,11.8 3.5,6.8 4.6,5.7 9,5.7 9.5,5.2 v1(10,5.2) 10.1,5.2 10.8,4.5 11.9,4.5 v1(12.6,5.2) 13,5.2 13.4,5.6 16,5.6 16.853,4.747 v1(16.853,4.547) ; v1@10.03,5.23 RP4.4.2@10.03,6.238 RP4.3.2@10.919,6.238 RP4.2.2@11.681,6.238 RP4.1.2@12.57,6.238 v1@12.57,5.23 ; 16.15,-29.25 Q3.5@16.15,-25.3 ; RP7.1.2@17.93,-16.338 RP7.2.2@18.819,-16.338 RP7.3.2@19.581,-16.338 RP7.4.2@20.47,-16.338 ; Q2.5@18.35,-0.3 v1@18.35,0.6 ; Q2.2@18.35,1.5 v1@18.35,0.6 ; v1(18.4,0.6) v1@18.35,0.6 ; 19.35,-29.25 Q4.5@19.35,-25.3 ; Q1.5@21.45,-0.3 Q1.2@21.45,1.5 ; v1(21.8,0.6) 25.6,0.6 26.262,1.262 RP5.4.2@26.262,2.03 RP5.3.2@26.262,2.919 RP5.2.2@26.262,3.681 RP5.1.2@26.262,4.57
  Top Layer w0.406: C4.1@5.2,29.2 5.2,28.6 v1(5.7,28.1) ; J4.1@12.7,-30.48 13.88,-29.3 21,-29.3 21.4,-28.9 21.4,-16.5 21.238,-16.338 RP7.4.2@20.47,-16.338 ; Q3.5@16.15,-25.3 Q3.2@16.15,-23.5 ; Q4.5@19.35,-25.3 Q4.2@19.35,-23.5
  Top Layer w0.508: v1(4.2,12.5) C3.1@4.2,13.3 ; v1(16.9,28.1) 16.9,28 17.4,27.5 C13.1@17.7,27.5
  Mid-Layer 1 w0.254: v1(16.853,4.547) 16.853,1.147 17.4,0.6 v1(18.4,0.6)
  Mid-Layer 1 w0.381: v1(5.7,28.1) 6,28.4
  Mid-Layer 1 w0.508: v2(-5.4,-17) -4.2,-15.8 -4.2,-9.3 1.1,-4 1.1,11.1 2.5,12.5 v1(4.2,12.5) ; v4(5.3,19.2) 7.5,21.4 7.5,28.118 ; 6,28.4 16.6,28.4 v1(16.9,28.1)
  Bottom Layer w0.254: RP1.1.2@-2.37,-24.062 RP1.2.2@-1.481,-24.062 -1.338,-24.062 RP1.3.2@-0.719,-24.062 ; v1(4.2,12.5) 4.9,11.8 U1.18@4.9,10.425 ; 8.6,28.1 8.6,27.5 9.3,26.8 9.834,26.8 10.1,26.534 U1.92@10.1,25.575 ; v1(10,5.2) 10.03,5.23 RP2.1.2@10.03,6.238 ; 11,28.1 11.3,27.8 U1.95@11.3,25.575 ; RP2.4.2@12.57,6.238 12.57,5.23 v1(12.6,5.2) ; v1(18.4,0.6) v1(21.8,0.6)
  Bottom Layer w0.305: 8.6,28.1 11,28.1
  Bottom Layer w0.406: v2(-5.4,-17) -5.4,-22.6 -3.938,-24.062 RP1.1.2@-2.37,-24.062 ; RP1.2.2@-1.338,-24.062 -0.281,-25.119 8.319,-25.119 12.7,-29.5 J4.1@12.7,-30.48 ; C15.1@5.2,29.2 5.2,28.6 v1(5.7,28.1)
  Bottom Layer w0.508: v2(-5.4,-17) -4.94,-16.54 L2.2@-1.9,-16.54 ; v1(4.2,12.5) 4.2,18.1 v4(5.3,19.2) ; v1(5.7,28.1) 8.6,28.1 ; v1(16.9,28.1) 16.9,28 17.4,27.5 C14.1@17.7,27.5
5V: C10.1 C48.1 C50.1 C51.1 C56.2 C57.1 J6.1 J9.1 J10.2 L3.1 L5.1 LED2.5 LED3.5 R10.2 R11.2 RP6.1.2 RP6.2.2 RP6.3.2 RP6.4.2 RP8.1.2 RP8.2.2 RP8.3.2 RP8.4.2 U1.102 U3.4 U3.6 U3.18 U4.5 U5.5 U6.8 Z1.2 | length 219.4
  Top Layer w0.406: v2(-24.7,-10.6) -24.7,-12.446 -23,-14.146 v2(-23,-22.1) ; v2(-22.7,-24.6) -21.6,-24.6 -19.1,-27.1 -19.1,-29.2 -17.82,-30.48 J10.2@-17.78,-30.48 -16.66,-31.6 -12.4,-31.6 -11.28,-30.48 J9.1@-10.16,-30.48 ; C57.1@-16.7,-6.6 -16.1,-6.6 -15.7,-7 ; U6.8@-14.712,-8.4 -14.712,-7.988 -15.7,-7 ; v1(-14.5,-7) -15.7,-7 ; R10.2@-10.1,3.1 -9.1,4.1 -6.6,4.1 v2(-6.4,3.9) ; v2(7.7,4.3) 8.6,4.3 9.4,3.5 v1(11,3.5) 11.9,2.6 13.458,2.6 14.529,3.671 v1(14.529,3.683) ; v2(17.4,-6.5) 17.33,-6.43 RP6.4.2@17.33,-5.462 RP6.3.2@18.219,-5.462 RP6.2.2@18.981,-5.462 RP6.1.2@19.87,-5.462
  Top Layer w0.61: LED3.5@-6.4,2.5 v2(-6.4,3.9) ; LED2.5@6.4,2.5 6.4,3.6 7.1,4.3 v2(7.7,4.3) ; v1(14.8,20.9) 14.3,20.4 12.3,20.4 11.8,19.9 11.8,16.1 14.8,13.1 C10.1@15.1,13.1
  Mid-Layer 1 w0.61: v2(7.7,4.3) 12.8,4.3 14.132,5.632 14.132,8.398 13.432,9.098 13.432,16.048 15.5,18.116 15.5,20.6 15.2,20.9 v1(14.8,20.9)
  Bottom Layer w0.254: U1.102@13.075,22.2 14.3,22.2 v1(14.8,21.7)
  Bottom Layer w0.406: v2(-24.7,-10.6) C50.1@-22.7,-10.6 ; v2(-23,-22.1) -22.7,-22.4 v2(-22.7,-24.6) ; v2@-22.7,-22.1 -22.7,-21.1 -21.5,-19.9 U3.4@-20.025,-19.9 -18.7,-19.9 -18.1,-19.3 ; U3.6@-20.025,-18.3 -18.6,-18.3 -18.1,-18.8 -18.1,-19.3 ; C48.1@-7.3,-19 -7.3,-18.3 -8.1,-17.5 -9.8,-17.5 U3.18@-11.775,-17.5 -12.7,-17.5 -13.4,-18.2 -13.4,-18.9 -13.8,-19.3 -18.1,-19.3 ; U5.5@9.6,2.3 10.7,2.3 ; v1(11,3.5) 11,2.6 10.7,2.3 ; C56.2@11.4,1.6 10.7,2.3 ; v1(14.529,3.683) 14.529,3.671 15.3,2.9 U4.5@15.3,2.3 15.7,2.3 16,2 16,-5.1 v2(17.4,-6.5) 21.4,-10.5 21.4,-20.808 RP8.1.2@20.27,-21.938 RP8.2.2@19.381,-21.938 RP8.3.2@18.619,-21.938 RP8.4.2@17.73,-21.938
  Bottom Layer w0.508: v1(14.8,20.9) v1(14.8,21.7)
  Bottom Layer w0.762: -11,-7.2 L3.1@-9.1,-7.2
  Bottom Layer w1.27: J6.1@-30,-5.7 J6.1@-23.9,-5.7 -23.6,-5.4 L5.1@-19,-5.4 ; J6.1@-22.7,-5.6 C50.1@-22.7,-10.6 C51.1@-18.4,-10.6 ; C51.1@-19,-10 L5.1@-19,-5.4 ; -19,-7.262 -11.062,-7.262 -11,-7.2 -6.5,-2.7 -6.5,3.8 v2(-6.4,3.9) -6,4.3 v2(7.7,4.3) ; Z1.2@-17.7,-2.272 -19,-3.572 L5.1@-19,-5.4
A0: U1.76 U2.29 | length 42.1
  Top Layer w0.152: v1@3,21.6 v1(3.1,21.6)
  Mid-Layer 1 w0.152: v1(-24.4,12.6) -24.4,13.6 -24.141,13.859 -23.781,13.5 -23.566,13.716 -23.925,14.075 -23.71,14.29 -23.411,13.991 -23.195,14.207 -23.494,14.506 -23.279,14.721 -22.979,14.422 -22.764,14.638 -23.063,14.937 -22.847,15.153 -22.548,14.853 -22.333,15.069 -22.632,15.368 -20.8,17.2 -8.415,17.2 -6.953,18.662 -4.16,18.662 -3.153,18.662 -1.215,20.6 2.4,20.6 3.1,21.3 v1(3.1,21.6)
  Bottom Layer w0.152: U2.29@-24.4,10.325 v1(-24.4,12.6) ; v1(3.1,21.6) 3.1,21.7 3.7,22.3 U1.76@3.7,25.575
A1: U1.75 U2.30 | length 42.1
  Mid-Layer 1 w0.152: v1(-25,13.1) -25.05,13.1 -25.05,13.35 -23.963,14.437 -24.215,14.689 -24,14.905 -23.747,14.653 -23.532,14.868 -23.784,15.12 -23.569,15.336 -23.316,15.084 -23.101,15.299 -23.353,15.552 -23.138,15.767 -22.885,15.515 -22.67,15.73 -22.922,15.983 -22.707,16.198 -22.454,15.946 -22.239,16.161 -22.491,16.414 -22.276,16.629 -22.023,16.377 -20.921,17.479 -8.53,17.479 -7.068,18.941 -4.044,18.941 ; -4.044,18.941 -3.269,18.941 0.711,22.921 2.279,22.921 2.703,22.497 v1(3.015,22.497)
  Bottom Layer w0.152: U2.30@-25.05,10.325 -25.05,13.1 v1(-25,13.1) ; v1(3.015,22.497) 3.015,22.615 3.3,22.9 U1.75@3.3,25.575
A2: U1.74 U2.31 | length 42.2
  Mid-Layer 1 w0.152: v1(-25.7,12.5) -25.7,13.6 -24.639,14.661 -24.876,14.898 -24.66,15.114 -24.423,14.877 -24.092,15.208 -24.418,15.533 -24.202,15.749 -23.877,15.423 -23.661,15.639 -23.987,15.964 -23.771,16.18 -23.446,15.854 -23.23,16.07 -23.556,16.395 -23.34,16.611 -23.015,16.285 -22.799,16.501 -23.125,16.826 -22.909,17.042 -22.584,16.716 -21.541,17.759 -8.646,17.759 -7.184,19.221 -3.929,19.221 -3.384,19.221 0.595,23.2 2.224,23.2 v1(2.527,23.503)
  Bottom Layer w0.152: U2.31@-25.7,10.325 v1(-25.7,12.5) ; v1(2.527,23.503) 2.527,23.627 2.9,24 U1.74@2.9,25.575
A3: U1.73 U2.32 | length 42.2
  Mid-Layer 1 w0.152: v1(-26.35,13.1) -26.35,14.15 -25.977,14.523 -25.685,14.232 -25.469,14.447 -26.053,15.031 -25.837,15.246 -25.546,14.954 -25.33,15.17 -25.622,15.462 -25.406,15.677 -25.115,15.385 -24.899,15.601 -25.191,15.893 -24.975,16.108 -24.684,15.816 -24.468,16.032 -24.76,16.324 -24.544,16.539 -24.253,16.247 -22.462,18.038 -8.762,18.038 -7.3,19.5 -3.813,19.5 -3.5,19.5 0.8,23.8 v1(1.8,23.8)
  Bottom Layer w0.152: U2.32@-26.35,10.325 -26.35,13.05 -26.325,13.075 v1@-26.3,13.1 ; v1(1.8,23.8) 2.5,24.5 U1.73@2.5,25.575
A4: U1.72 U2.35 | length 42.1
  Top Layer w0.152: v1(-26.3,23.7) -20.897,29.103 -13.515,29.103 -13.515,28.849 -13.21,28.849 -13.21,29.357 -12.905,29.357 -12.905,28.849 -12.6,28.849 -12.6,29.357 -12.296,29.357 -12.296,28.849 -11.991,28.849 -11.991,29.357 -11.686,29.357 -11.686,28.849 -11.381,28.849 -11.381,29.357 -11.076,29.357 -11.076,28.849 -10.772,28.849 -10.772,29.357 -10.467,29.357 -10.467,28.849 -10.162,28.849 -10.162,29.357 -9.857,29.357 -9.857,28.849 -9.552,28.849 -9.552,29.103 -2.603,29.103 v1(-2.3,28.8)
  Bottom Layer w0.152: U2.35@-26.35,21.675 -26.3,21.725 v1(-26.3,23.7) ; v1(-2.3,28.8) 1.2,28.8 2.1,27.9 U1.72@2.1,25.575
A5: U1.71 U2.36 | length 42.1
  Top Layer w0.152: v1(-25.7,23.1) -25.7,23.712 -20.912,28.5 -20.448,28.5 -20.448,28.808 -20.143,28.808 -20.143,28.008 -19.838,28.008 -19.838,28.808 -19.533,28.808 -19.533,28.008 -19.228,28.008 -19.228,28.808 -18.924,28.808 -18.924,28.008 -18.619,28.008 -18.619,28.808 -18.314,28.808 -18.314,28.008 -18.009,28.008 -18.009,28.808 -17.704,28.808 -17.704,28.5 -16.909,28.5 -16.506,28.097 -14.903,28.097 -14.6,28.4 -5.162,28.4 -5.162,28.705 -4.857,28.705 -4.857,28.4 -3.8,28.4 v1@-3.65,28.25
  Bottom Layer w0.152: U2.36@-25.7,21.675 -25.7,22.9 -25.6,23 -25.5,23.1 v1(-25.7,23.1) ; v1@-3.7,28.297 -3.6,28.297 1.103,28.297 1.7,27.7 U1.71@1.7,25.575
  other v1: -3.6,28.3
A6: U1.70 U2.37 | length 41.8
  Top Layer w0.152: v1(-25,23.7) -21,27.7 -14.148,27.7 -14.148,28.099 -13.843,28.099 -13.843,27.7 -13.538,27.7 -13.538,28.099 -13.233,28.099 -13.233,27.7 -12.928,27.7 -12.928,28.099 -12.624,28.099 -12.624,27.7 -12.319,27.7 -12.319,28.099 -12.014,28.099 -12.014,27.7 -11.709,27.7 -11.709,28.099 -11.404,28.099 -11.404,27.7 -11.1,27.7 -11.1,28.099 -10.795,28.099 -10.795,27.7 -10.49,27.7 -10.49,28.099 -10.185,28.099 -10.185,27.7 -9.88,27.7 -9.88,28.099 -9.576,28.099 -9.576,27.7 -9.271,27.7 -9.271,28.099 -8.966,28.099 -8.966,27.7 -8.661,27.7 -8.661,28.099 -8.356,28.099 -8.356,27.7 -8.052,27.7 -8.052,28.099 -7.747,28.099 -7.747,27.7 -7.442,27.7 -7.442,28.099 -7.137,28.099 -7.137,27.7 v1(-5,27.7)
  Bottom Layer w0.152: U2.37@-25.028,21.675 U2.37@-25.05,21.675 -25.05,23.65 v1(-25,23.7) ; v1(-5,27.7) -4.997,27.697 -3.003,27.697 -2.7,28 0.7,28 1.3,27.4 U1.70@1.3,25.575
A7: U1.69 U2.38 | length 41.8
  Top Layer w0.152: v1(-24.4,23.1) -24.4,23.712 -20.912,27.2 -20.412,27.2 -20.408,27.204 -19.992,27.204 -19.988,27.2 -16.22,27.2 -16.22,26.893 -15.916,26.893 -15.916,27.2 -15.611,27.2 -15.611,26.893 -15.306,26.893 -15.306,27.2 -15.001,27.2 -15.001,26.893 -14.696,26.893 -14.696,27.2 -14.392,27.2 -14.392,26.893 -14.087,26.893 -14.087,27.2 -13.782,27.2 -13.782,26.893 -13.477,26.893 -13.477,27.2 -13.172,27.2 -13.172,26.893 -12.41,26.893 -12.41,27.373 -12.106,27.373 -12.106,26.893 -11.801,26.893 -11.801,27.373 -11.496,27.373 -11.496,26.893 -11.191,26.893 -11.191,27.373 -10.886,27.373 -10.886,26.893 -10.582,26.893 -10.582,27.373 -10.277,27.373 -10.277,26.893 -9.972,26.893 -9.972,27.373 -9.667,27.373 -9.667,26.893 -9.362,26.893 -9.362,27.373 -9.058,27.373 -9.058,26.893 -8.753,26.893 -8.753,27.373 -8.448,27.373 -8.448,26.893 -8.143,26.893 -8.143,27.373 -7.838,27.373 -7.838,26.893 -5.807,26.893 -5.503,27.197 v1@-3.697,27.197
  Bottom Layer w0.152: U2.38@-24.4,21.675 v1(-24.4,23.1) ; v1(-3.6,27.1) -3,27.1 -2.5,27.6 0.4,27.6 0.9,27.1 U1.69@0.9,25.575
A8: U1.68 U2.39 | length 41.8
  Top Layer w0.152: v1(-23.7,23.6) -23.7,23.9 -21.562,26.038 -19.755,26.038 -19.194,26.6 -17.64,26.6 -17.64,26.109 -17.335,26.109 -17.335,26.905 -17.03,26.905 -17.03,26.109 -16.725,26.109 -16.725,26.6 -16.42,26.6 -16.42,26.109 -16.116,26.109 -16.116,26.6 -15.811,26.6 -15.811,26.109 -15.506,26.109 -15.506,26.6 -15.201,26.6 -15.201,26.109 -14.896,26.109 -14.896,26.6 -9.715,26.6 -9.715,26.109 -9.41,26.109 -9.41,26.6 -9.105,26.6 -9.105,26.109 -8.8,26.109 -8.8,26.6 -8.496,26.6 -8.496,26.109 -8.191,26.109 -8.191,26.6 -7.886,26.6 -7.886,26.109 -7.581,26.109 -7.581,26.6 -7.276,26.6 -7.276,26.109 -6.972,26.109 -6.972,26.6 -6.667,26.6 -6.667,26.109 -6.362,26.109 -6.362,26.6 -6.057,26.6 -6.057,26.109 -5.752,26.109 -5.752,26.6 v1(-5,26.6)
  Bottom Layer w0.152: U2.39@-23.75,21.675 v1@-23.75,23.6 ; v1(-5,26.6) -4.012,26.6 -4.008,26.597 -2.803,26.597 -2.079,27.321 0.179,27.321 0.5,27 U1.68@0.5,25.575
A9: U1.67 U2.40 | length 41.8
  Top Layer w0.152: v1(-23.1,23) -23.1,24 -21.341,25.759 -14.048,25.759 -14.048,26.249 -13.743,26.249 -13.743,25.268 -13.438,25.268 -13.438,26.249 -13.133,26.249 -13.133,25.268 -12.828,25.268 -12.828,26.249 -12.524,26.249 -12.524,25.268 -12.219,25.268 -12.219,26.249 -11.914,26.249 -11.914,25.268 -11.609,25.268 -11.609,26.249 -11.304,26.249 -11.304,25.268 -11,25.268 -11,26.249 -10.695,26.249 -10.695,25.268 -10.39,25.268 -10.39,26.249 -10.085,26.249 -10.085,25.268 -9.78,25.268 -9.78,25.759 -3.841,25.759 v1(-3.6,26)
  Bottom Layer w0.152: U2.40@-23.1,21.675 v1(-23.1,23) ; v1(-3.6,26) -2.7,26 -1.7,27 -0.1,27 0.1,26.8 U1.67@0.1,25.575
A10: U1.66 U2.28 | length 42.2
  Mid-Layer 1 w0.152: v1(-23.7,18.7) -20.4,22 -3.6,22 -1.8,23.8 v1(-0.2,23.8)
  Bottom Layer w0.152: U2.28@-23.75,10.325 -23.75,15.714 -23.301,15.714 -23.301,16.019 -24.199,16.019 -24.199,16.324 -23.301,16.324 -23.301,16.628 -24.199,16.628 -24.199,16.933 -23.301,16.933 -23.301,17.238 -24.199,17.238 -24.199,17.543 -23.301,17.543 -23.301,17.848 -23.75,17.848 -23.75,18.7 v1@-23.75,18.725 ; v1@-23.75,18.75 v1(-23.7,18.7) ; U1.66@-0.3,25.575 -0.3,23.9 v1(-0.2,23.8)
A11: U1.65 U2.41 | length 41.8
  Top Layer w0.152: v1(-22.45,23.65) -22.45,24.05 -21.6,24.9 -20.848,24.9 -20.848,25.396 -20.543,25.396 -20.543,24.404 -20.238,24.404 -20.238,25.396 -19.933,25.396 -19.933,24.404 -19.628,24.404 -19.628,25.396 -19.324,25.396 -19.324,24.404 -19.019,24.404 -19.019,25.396 -18.714,25.396 -18.714,24.404 -18.409,24.404 -18.409,25.396 -18.104,25.396 -18.104,24.404 -17.8,24.404 -17.8,25.396 -17.495,25.396 -17.495,24.404 -17.19,24.404 -17.19,25.396 -16.885,25.396 -16.885,24.404 -16.58,24.404 -16.58,25.396 -16.276,25.396 -16.276,24.404 -15.971,24.404 -15.971,25.396 -15.666,25.396 -15.666,24.9 -9.6,24.9 -9.2,25.3 -2.7,25.3 -2.2,25.8 v1(-1.6,25.8)
  Bottom Layer w0.152: U2.41@-22.45,21.675 v1(-22.45,23.65) ; v1(-1.6,25.8) -1.4,25.8 -1.175,25.575 U1.65@-0.7,25.575
A12: U1.64 U2.42 | length 41.7
  Top Layer w0.152: v1(-21.8,23) -21.8,23.3 -21.1,24 -20.643,24 -20.643,23.492 -20.338,23.492 -20.338,24 -20.033,24 -20.033,23.492 -19.728,23.492 -19.728,24 -19.424,24 -19.424,23.492 -19.119,23.492 -19.119,24 -18.814,24 -18.814,23.693 -18.509,23.693 -18.509,24 -15.448,24 -15.448,24.508 -15.143,24.508 -15.143,24 -14.838,24 -14.838,24.508 -14.533,24.508 -14.533,24 -14.228,24 -14.228,24.508 -13.924,24.508 -13.924,24 -13.619,24 -13.619,24.508 -13.314,24.508 -13.314,24 -13.009,24 -13.009,24.508 -12.704,24.508 -12.704,24 -12.4,24 -12.4,24.508 -12.095,24.508 -12.095,24 -11.79,24 -11.79,24.508 -11.485,24.508 -11.485,24 -11.18,24 -11.18,24.508 -10.876,24.508 -10.876,24 -10.571,24 -10.571,24.508 -10.266,24.508 -10.266,24 -9.961,24 -9.961,24.508 -9.656,24.508 -9.656,24 -9.352,24 -9.352,24.7 -9.047,24.7 -9.047,24 -8.742,24 -8.742,24.7 -8.437,24.7 -8.437,24 -8.132,24 -8.132,24.7 -7.828,24.7 -7.828,24 -7.523,24 -7.523,24.7 -7.218,24.7 -7.218,24 -7,24 -6.097,24.903 -4.703,24.903 v1(-4,24.2)
  Bottom Layer w0.152: U2.42@-21.8,21.675 v1(-21.8,23) ; v1(-4,24.2) U1.64@-2.075,24.2
A_RXD: D6.1 Q2.4 RP4.1.1 RP5.1.1 U1.128 | length 27.8
  Top Layer w0.254: RP4.1.1@12.57,7.762 13.362,7.762 v1(13.4,7.8) ; v1(17.6,-1.1) Q2.4@17.6,-0.3 ; v1(17.6,2.8) 19.37,4.57 RP5.1.1@24.738,4.57 24.738,5.338 25.7,6.3 D6.1@26.4,6.3
  Bottom Layer w0.254: U1.128@13.075,11.8 13.4,11.475 v1(13.4,7.8) 15.216,5.984 16.368,5.984 17.6,4.752 v1(17.6,2.8) v1(17.6,-1.1)
A_RXD_5V: Q2.3 RP6.4.1 U3.31 | length 61.7
  Top Layer w0.254: v1(6,-7.2) 7.513,-5.687 14.513,-5.687 16.262,-3.938 RP6.4.1@17.33,-3.938 17.33,-3.23 16.9,-2.8 16.9,1.1 17.3,1.5 Q2.3@17.6,1.5
  Mid-Layer 1 w0.254: v1(-17,-20.3) -16.946,-20.246 -13.354,-20.246 -10.6,-23 4,-23 5.5,-21.5 5.5,-17.9 6.554,-16.846 6.554,-8.454 6,-7.9 v1(6,-7.2)
  Bottom Layer w0.254: U3.31@-17.9,-23.625 -17.9,-21.2 v1(-17,-20.3)
A_TXD: J12.2 Q2.1 RP5.2.1 U1.127 | length 34.6
  Top Layer w0.254: Q2.1@19.1,1.5 v1(19.1,2.5) 19.5,2.5 20.681,3.681 RP5.2.1@24.738,3.681
  Bottom Layer w0.254: U1.127@13.075,12.2 14.1,12.2 14.3,12 14.3,11.1 13.792,10.592 13.792,8.611 16.038,6.365 16.557,6.365 19.1,3.822 v1(19.1,2.5)
  Bottom Layer w0.406: v1(23.1,3.7) 23.1,4.4 24.5,5.8 24.5,9.9 27.3,12.7 J12.2@30.48,12.7
A_TXD_5V: Q2.6 RP6.3.1 U3.30 | length 59.6
  Top Layer w0.254: v1(6.935,-7.235) 6.935,-7.065 7.932,-6.068 15.132,-6.068 v1(15.4,-5.8) ; RP6.3.1@18.219,-3.938 v1(18.219,-2.7) 18.219,-1.681 19.1,-0.8 Q2.6@19.1,-0.3
  Mid-Layer 1 w0.254: v1(-15.1,-20.8) -13.6,-20.8 -10.9,-23.5 4.3,-23.5 6,-21.8 6,-18.1 6.935,-17.165 v1(6.935,-7.235) ; v1(15.4,-5.8) 18.2,-3 18.2,-2.719 v1(18.219,-2.7)
  Bottom Layer w0.254: U3.30@-17.1,-23.625 -17.1,-21.7 -16.2,-20.8 v1(-15.1,-20.8)
BA0: U1.79 U2.26 | length 42.2
  Mid-Layer 1 w0.152: v1(-22.5,13.5) -22.5,14.112 -21.933,14.679 -21.644,14.391 -21.429,14.606 -21.717,14.895 -21.501,15.11 -21.213,14.822 -20.998,15.037 -21.286,15.326 -19.97,16.641 -19.513,16.641 -19.513,16.234 -19.208,16.234 -19.208,16.641 -18.904,16.641 -18.904,16.234 -18.599,16.234 -18.599,16.641 -8.183,16.641 -6.721,18.103 -4.392,18.103 -0.009,18.103 0.408,18.103 0.71,18.103 3.557,20.95 4.3,20.95 v1@4.35,20.95
  Bottom Layer w0.152: v1(-22.5,13.5) -22.45,13.45 -22.45,12.062 -22.145,12.062 -22.145,11.757 -22.45,11.757 U2.26@-22.45,10.325 ; v1(4.3,21) 4.897,21.597 4.897,25.572 U1.79@4.9,25.575
BA1: U1.80 U2.27 | length 42.2
  Mid-Layer 1 w0.152: v1(-23.1,12.8) -23.1,13.907 -21.654,15.352 -21.914,15.612 -21.699,15.828 -21.439,15.568 -21.223,15.784 -21.483,16.044 -21.268,16.259 -21.008,15.999 -20.792,16.215 -21.052,16.475 -20.837,16.69 -20.577,16.43 -20.086,16.921 -8.299,16.921 -6.837,18.383 -4.276,18.383 -0.124,18.382 0.524,18.383 0.594,18.382 3.441,21.229 3.729,21.229 4.012,21.512 5.112,21.512 v1(5.4,21.8)
  Bottom Layer w0.152: U2.27@-23.1,10.325 -23.1,11.652 -22.795,11.652 -22.795,11.957 -23.1,11.957 v1(-23.1,12.8) ; U1.80@5.3,25.575 5.3,21.8 5.3,21.7 v1(5.4,21.8)
CAS_N: U1.61 U2.22 | length 42.2
  Top Layer w0.152: v1(-19.75,14.65) -19.75,15.204 -19.242,15.204 -19.242,15.509 -19.75,15.509 -19.75,15.814 -19.242,15.814 -19.242,16.119 -20.258,16.119 -20.258,16.424 -19.242,16.424 -19.242,16.728 -20.258,16.728 -20.258,17.033 -19.242,17.033 -19.242,17.338 -20.258,17.338 -20.258,17.643 -19.242,17.643 -19.242,17.948 -19.75,17.948 -19.75,18.25 -19.88,18.38 -20.186,18.074 -20.401,18.29 -20.096,18.596 -19.79,18.901 -20.006,19.117 -20.311,18.811 -20.527,19.027 -20.311,19.242 -20.527,19.458 -20.742,19.242 -21.003,19.503 -21.003,20.212 -21,20.215 -21,21.1 -20.083,22.017 -4.683,22.017 v1(-3.9,22.8)
  Bottom Layer w0.152: U2.22@-19.85,10.325 -19.85,13.743 -19.545,13.743 -19.545,14.048 -19.85,14.048 -19.85,14.65 v1(-19.75,14.65) ; v1(-3.9,22.8) -3.7,23 U1.61@-2.075,23
CKE: U1.78 U2.44 | length 42.1
  Top Layer w0.152: v1(-20.5,20) -20.5,21 -19.8,21.7 -19.343,21.7 -19.343,21.192 -19.038,21.192 -19.038,21.7 -18.733,21.7 -18.733,21.192 -18.428,21.192 -18.428,21.7 -18.124,21.7 -18.124,21.192 -17.819,21.192 -17.819,21.7 -17.514,21.7 -17.514,21.192 -17.209,21.192 -17.209,21.7 -16.904,21.7 -16.904,21.192 -16.6,21.192 -16.6,21.7 -16.295,21.7 -16.295,21.192 -15.99,21.192 -15.99,21.7 -15.685,21.7 -15.685,21.192 -15.38,21.192 -15.38,21.7 -15.076,21.7 -15.076,21.192 -14.771,21.192 -14.771,21.7 -14.466,21.7 -14.466,21.192 -14.161,21.192 -14.161,21.7 -13.856,21.7 -13.856,21.192 -13.552,21.192 -13.552,21.7 -13.247,21.7 -13.247,21.353 -12.942,21.353 -12.942,21.7 -4.512,21.7 -4.308,21.903 -3.197,21.903 -2.1,23 -1.448,23 -1.448,23.33 -1.143,23.33 -1.143,23 3.7,23 v1(4.3,23.6)
  Bottom Layer w0.152: v1(-20.5,20) U2.44@-20.5,21.675 ; v1(4.3,23.6) 4.3,23.8 4.5,24 U1.78@4.5,25.575
CLK_N: R3.1 U1.37 U2.46 | length 26.7
  Mid-Layer 1 w0.152: v1(-17.3,16) -17.4,16 -17.35,15.95 -13.6,12.2 -5.312,12.2 -5.108,12.403 -4.997,12.403 v1(-4.7,12.7)
  Bottom Layer w0.152: R3.1@-18.7,23.6 -19.2,23.1 U2.46@-19.2,21.675 -19.2,20.9 -19.4,20.7 -19.4,19.895 -18.121,18.616 -18.121,16.721 -17.4,16 v1(-17.3,16) ; v1(-4.7,12.7) -4.4,12.4 -4.1,12.4 -3.85,12.65 -3.85,12.95 -3.65,13.15 -3.35,13.15 -3.1,13.4 U1.37@-2.075,13.4
CLK_P: R3.2 U1.36 U2.45 | length 26.7
  Mid-Layer 1 w0.152: v1@-18.006,15.994 -17.508,15.497 -17.397,15.497 -13.8,11.9 v1(-4.9,11.9)
  Bottom Layer w0.152: R3.2@-20.4,23.6 -19.85,23.05 U2.45@-19.85,21.675 -19.85,19.95 -18.4,18.5 -18.4,16.5 -18.1,16.2 v1(-18.1,15.9) ; v1(-4.9,11.9) -4.2,11.9 -3.1,13 U1.36@-2.075,13
CS_N: R2.1 U1.63 U2.24 | length 42.1
  Top Layer w0.152: v1(-21.1,13.2) -21.859,13.959 -21.859,15.89 -22.367,15.89 -22.367,16.195 -21.859,16.195 -21.859,16.5 -22.367,16.5 -22.367,16.804 -21.859,16.804 -21.859,17.109 -22.367,17.109 -22.367,17.414 -21.859,17.414 -21.859,17.719 -22.367,17.719 -22.367,18.024 -21.859,18.024 -21.859,18.328 -22.367,18.328 -22.367,18.633 -21.859,18.633 -21.859,18.938 -22.367,18.938 -22.367,19.243 -21.859,19.243 -21.859,20.005 -22.322,20.005 -22.322,20.31 -21.859,20.31 -21.859,21.541 -20.5,22.9 -18.9,22.9 -18.683,23.117 -18.683,23.124 -18.224,23.583 -18.217,23.583 -18.1,23.7 -6.2,23.7 v1(-5.5,24.4)
  Bottom Layer w0.152: U2.24@-21.1,10.375 v1(-21.1,13.2) ; v1(-5.5,24.4) -4.797,23.697 -3.792,23.697 -3.688,23.8 U1.63@-2.075,23.8
  Bottom Layer w0.254: R2.1@-22.1,8.4 -21.15,9.35 U2.24@-21.15,10.325
D0: U1.41 U2.2 | length 20.9
  Top Layer w0.152: v1(-6.8,13.3) -6.8,13.5 -6.6,13.7 -5.843,13.7 -5.843,13.233 -5.538,13.233 -5.538,13.7 -5.233,13.7 -5.233,13.233 -4.928,13.233 -4.928,13.7 -4.624,13.7 -4.624,13.238 -4.319,13.238 -4.319,13.7 -4.014,13.7 -4.014,13.233 -3.709,13.233 -3.709,13.7 -3.404,13.7 -3.404,13.233 -3.1,13.233 -3.1,13.7 -2.795,13.7 -2.795,13.233 -2.49,13.233 -2.49,13.7 -2.185,13.7 -2.185,13.233 -1.88,13.233 -1.88,13.7 0.128,13.7 v1(0.782,14.354)
  Bottom Layer w0.152: U2.2@-6.8,10.375 v1(-6.8,13.3) v1@-6.8,13.5 ; U1.41@-2.075,15 -2.054,14.979 -1.095,14.979 -0.462,14.346 0.774,14.346 v1(0.782,14.354)
D1: U1.43 U2.4 | length 20.9
  Top Layer w0.152: v1(-7.7,14.7) -7.5,14.9 -4.59,14.9 -4.59,14.4 -4.184,14.4 -4.184,14.9 -3.778,14.9 -3.778,14.4 -3.371,14.4 -3.371,14.9 -2.965,14.9 -2.965,14.4 -2.558,14.4 -2.558,14.9 -2.152,14.9 -2.152,14.4 -1.746,14.4 -1.746,14.9 -1.31,14.9 -1.31,14.595 -0.903,14.595 -0.903,14.9 -0.412,14.9 0.488,15.8 v1(0.7,15.8)
  Bottom Layer w0.152: U2.4@-8.15,10.325 -8.15,12.55 -8.297,12.697 -8.297,13.712 -8.3,13.715 -8.3,14.1 v1(-7.7,14.7) ; U1.43@-2.075,15.8 v1(0.7,15.8)
D2: U1.42 U2.5 | length 21.1
  Top Layer w0.152: v1(-8.8,13.5) -8.8,13.8 -8.6,14 -7.138,14 -7.138,14.508 -6.833,14.508 -6.833,14 -6.528,14 -6.528,14.508 -6.224,14.508 -6.224,14 -5.919,14 -5.919,14.508 -5.614,14.508 -5.614,14 -5.309,14 -5.309,14.508 -5.004,14.508 -5.004,14 -0.6,14 v1(0.3,14.9)
  Mid-Layer 1 w0.152: v1(0.3,14.9) v1@0.3,15.1
  Bottom Layer w0.152: U2.5@-8.8,10.325 -8.8,11.452 -9.251,11.452 -9.251,11.757 -8.8,11.757 v1(-8.8,13.5) v1@-8.8,13.8 ; U1.42@-2.075,15.4 -0.2,15.4 v1(0.3,14.9)
D3: U1.44 U2.7 | length 21.1
  Top Layer w0.152: v1(-10.083,14.283) -10.083,14.3 -8.98,15.403 -2.102,15.403 -1.151,16.354 0.054,16.354 0.15,16.45 0.2,16.5 v1(0.2,16.4)
  Bottom Layer w0.152: U2.7@-10.1,10.325 -10.1,11.603 -10.416,11.603 -10.416,12.01 -9.655,12.01 -9.655,12.416 -10.1,12.416 -10.1,12.873 -9.795,12.873 -9.795,13.178 -10.405,13.178 -10.405,13.483 -9.795,13.483 -9.795,13.788 -10.1,13.788 v1@-10.1,14.267 ; U1.44@-2.075,16.2 -0.1,16.2 0.15,16.45 0.2,16.5 v1(0.2,16.4)
D4: U1.47 U2.8 | length 21.1
  Top Layer w0.152: v1(-10.7,15.1) -10.118,15.682 -2.218,15.682 -0.3,17.6 v1(0.2,17.6)
  Bottom Layer w0.152: U2.8@-10.75,10.325 -10.75,11.852 -11.214,11.852 -11.214,12.157 -10.75,12.157 -10.75,12.462 -11.214,12.462 -11.214,12.767 -10.75,12.767 -10.75,15.05 v1(-10.7,15.1) ; U1.47@-2.075,17.4 0.1,17.4 v1@0.2,17.5 ; v1@0.2,17.4 v1@0.2,17.5 ; v1(0.2,17.6) v1@0.2,17.5
D5: U1.48 U2.10 | length 21.1
  Top Layer w0.152: v1(-11.8,15.6) -11.8,15.5 -11.75,15.55 -11.338,15.962 -4.238,15.962 v1(-3.9,16.3)
  Bottom Layer w0.152: U2.10@-12.1,10.375 U2.10@-12.05,10.325 -12.05,12.052 -12.355,12.052 -12.355,12.357 -11.62,12.357 -11.62,12.662 -12.355,12.662 -12.355,12.967 -11.62,12.967 -11.62,13.272 -12.355,13.272 -12.355,13.576 -11.62,13.576 -11.62,13.881 -12.05,13.881 -12.05,15.25 -11.8,15.5 v1(-11.8,15.6) ; v1(-3.9,16.3) -3.9,17.1 -3.2,17.8 U1.48@-2.075,17.8
D6: U1.49 U2.11 | length 21.1
  Top Layer w0.152: v1@-12.744,15.756 -12.259,16.241 -5.159,16.241 v1(-4.6,16.8) ; v1(-12.7,15.7) -12.688,15.7 v1@-12.603,15.615
  Bottom Layer w0.152: U2.11@-12.7,10.325 -12.7,13.019 -13.149,13.019 -13.149,13.324 -12.7,13.324 -12.7,13.628 -13.149,13.628 -13.149,13.933 -12.395,13.933 -12.395,14.238 -13.149,14.238 -13.149,14.543 -12.395,14.543 -12.395,14.848 -12.7,14.848 v1(-12.7,15.7) ; v1(-4.6,16.8) -3.508,17.892 -3.2,18.2 U1.49@-2.075,18.2
D7: U1.50 U2.13 | length 21
  Top Layer w0.152: v1(-13.4,15.5) -13.4,15.712 -12.591,16.521 -5.779,16.521 -4.8,17.5 -4.7,17.5 v1(-4.6,17.6)
  Bottom Layer w0.152: U2.13@-14,10.325 -14,12.403 -14.4,12.403 -14.4,12.81 -14,12.81 -14,13.216 -14.4,13.216 -14.4,13.622 -14,13.622 -14,14.08 -14.508,14.08 -14.508,14.384 -14,14.384 -14,14.9 v1(-13.4,15.5) ; v1@-4.8,17.5 -4.65,17.65 -3.7,18.6 U1.50@-2.075,18.6
D8: U1.51 U2.54 | length 21
  Top Layer w0.152: v1(-14,19.5) -14,18.198 -13.746,18.198 -13.746,17.893 -14,17.893 -14,17.2 -13.6,16.8 -13.248,16.8 -13.248,17.308 -12.943,17.308 -12.943,16.8 -12.638,16.8 -12.638,17.308 -12.333,17.308 -12.333,16.8 -12.028,16.8 -12.028,17.308 -11.724,17.308 -11.724,16.8 -6.3,16.8 v1(-6,17.1)
  Bottom Layer w0.152: v1(-14,19.5) U2.54@-14,21.675 ; v1(-6,17.1) -4.1,19 U1.51@-2.075,19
